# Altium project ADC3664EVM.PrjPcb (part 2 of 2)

## Sheet ADC Inputs.SchDoc: ADC Inputs
size 431 x 279 mm; Date: Not shown in title block; ApprovedBy: Not shown in title block; CheckedBy: Not shown in title block; Author: Not shown in title block; CompanyName: Not shown in title block; Engineer: Not shown in title block; Organization: Not shown in title block; Address1: Not shown in title block; Address2: Not shown in title block; Address3: Not shown in title block; Address4: Not shown in title block; DocumentNumber: 1; Revision: Use project parameter SCH_Rev; SheetNumber: 9; SheetTotal: 14; PageSetup: Record=PageOptions¦CenterHorizontal=True¦CenterVertical=True¦PrintScale=1.00¦XCorrection=1.00¦YCorrection=1.00¦PrintKind=0¦BorderSize=5000000¦LeftOffset=0¦BottomOffset=0¦Orientation=2¦PaperLength=1000¦PaperWidth=1000¦Scale=100¦PaperSource=15¦PrintQuality=600¦MediaType=1¦DitherType=10¦PaperKind=Letter¦PrintScaleMode=1
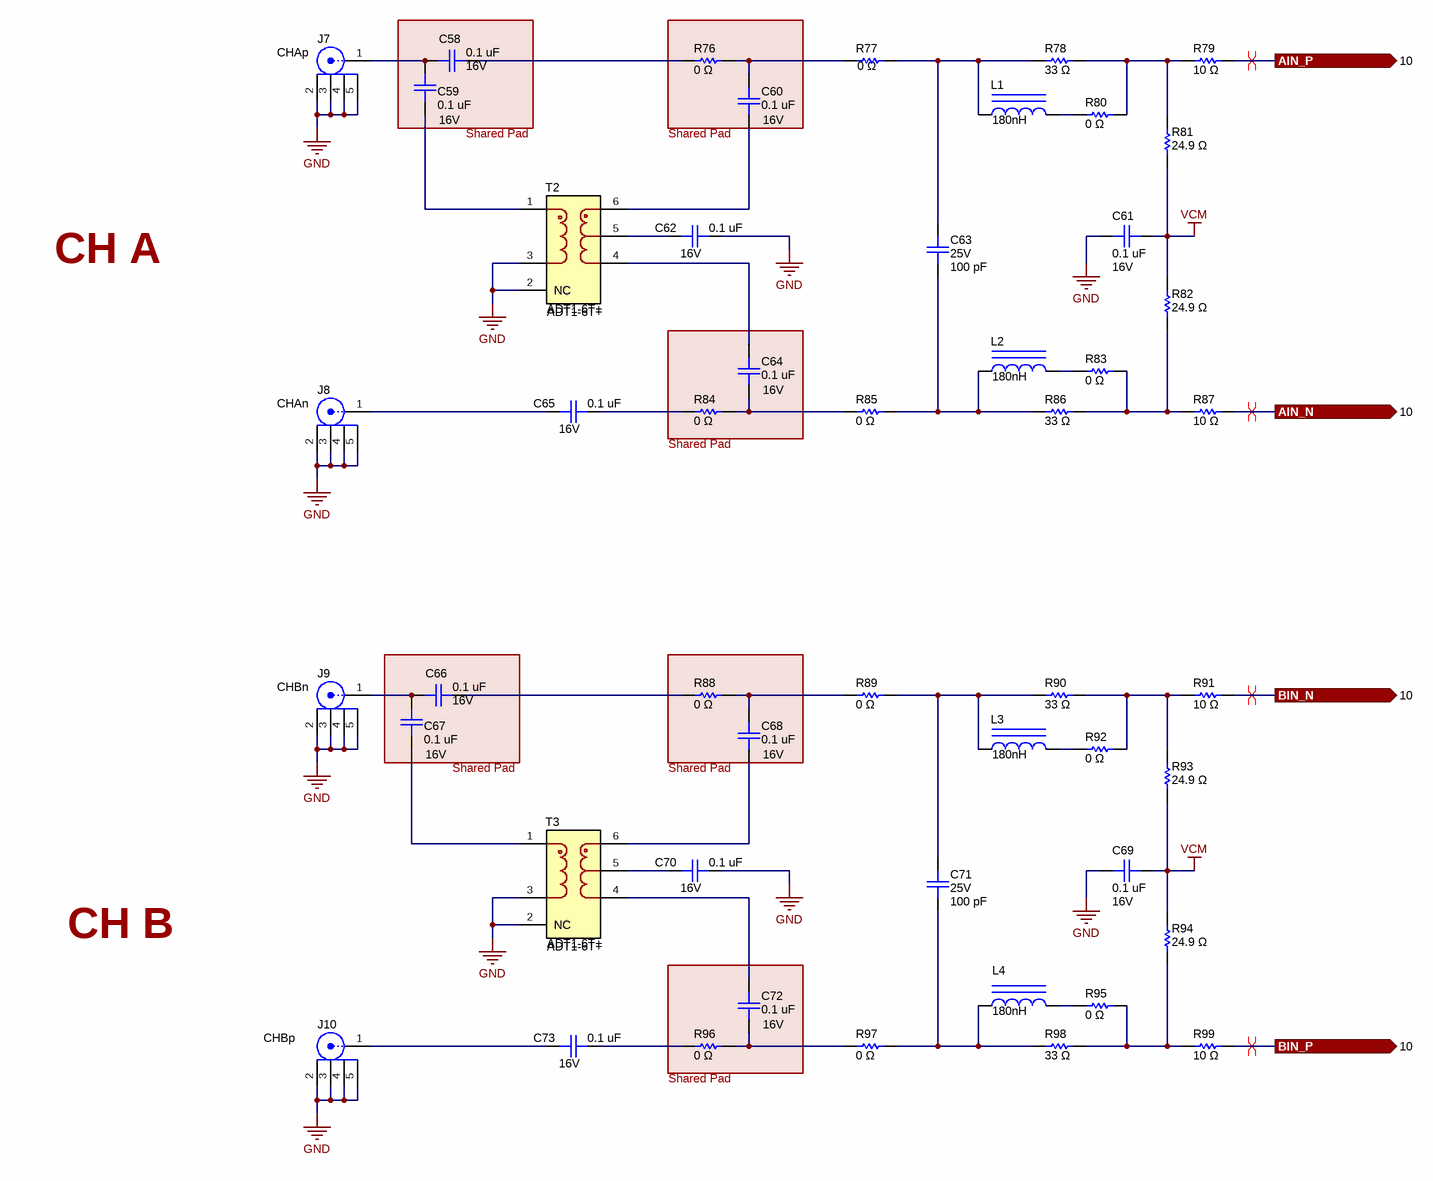
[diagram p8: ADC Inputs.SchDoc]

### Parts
(Parts that share a designator on the sheet are numbered #1, #2 ... from top to bottom, then left to right.)
?#4  Shared Pad  (graphical)
?#5  Shared Pad  (graphical)
?#6  Shared Pad  (graphical)
?#7  Shared Pad  (graphical)
?#8  Shared Pad  (graphical)
?#9  Shared Pad  (graphical)
C58  value 0.1 uF  Voltage - Rated: 16V  [0201_cap]  (hidden comment: GRM033Z71C104ME14D)
C59  value 0.1 uF  Voltage - Rated: 16V  [0201_cap]  (hidden comment: GRM033Z71C104ME14D)
C60  value 0.1 uF  Voltage - Rated: 16V  [0201_cap]  (hidden comment: GRM033Z71C104ME14D)
C61  value 0.1 uF  Voltage - Rated: 16V  [0201_cap]  (hidden comment: GRM033Z71C104ME14D)
C62  value 0.1 uF  Voltage - Rated: 16V  [0201_cap]  (hidden comment: GRM033Z71C104ME14D)
C63  value 100 pF  Voltage - Rated: 25V  [0201_cap]  (hidden comment: CGA1A2X7R1E101M030BA)
C64  value 0.1 uF  Voltage - Rated: 16V  [0201_cap]  (hidden comment: GRM033Z71C104ME14D)
C65  value 0.1 uF  Voltage - Rated: 16V  [0201_cap]  (hidden comment: GRM033Z71C104ME14D)
C66  value 0.1 uF  Voltage - Rated: 16V  [0201_cap]  (hidden comment: GRM033Z71C104ME14D)
C67  value 0.1 uF  Voltage - Rated: 16V  [0201_cap]  (hidden comment: GRM033Z71C104ME14D)
C68  value 0.1 uF  Voltage - Rated: 16V  [0201_cap]  (hidden comment: GRM033Z71C104ME14D)
C69  value 0.1 uF  Voltage - Rated: 16V  [0201_cap]  (hidden comment: GRM033Z71C104ME14D)
C70  value 0.1 uF  Voltage - Rated: 16V  [0201_cap]  (hidden comment: GRM033Z71C104ME14D)
C71  value 100 pF  Voltage - Rated: 25V  [0201_cap]  (hidden comment: CGA1A2X7R1E101M030BA)
C72  value 0.1 uF  Voltage - Rated: 16V  [0201_cap]  (hidden comment: GRM033Z71C104ME14D)
C73  value 0.1 uF  Voltage - Rated: 16V  [0201_cap]  (hidden comment: GRM033Z71C104ME14D)
J7  Text1: CHAp  [FP-132134-15_CONN_SMA_JACK-MFG]  (hidden comment: 132134-15)
J8  Text1: CHAn  [FP-132134-15_CONN_SMA_JACK-MFG]  (hidden comment: 132134-15)
J9  Text1: CHBn  [FP-132134-15_CONN_SMA_JACK-MFG]  (hidden comment: 132134-15)
J10  Text1: CHBp  [FP-132134-15_CONN_SMA_JACK-MFG]  (hidden comment: 132134-15)
L1  value 180nH  [IND_LQG15H]  (hidden comment: LQG15HSR18J02D)
L2  value 180nH  [IND_LQG15H]  (hidden comment: LQG15HSR18J02D)
L3  value 180nH  [IND_LQG15H]  (hidden comment: LQG15HSR18J02D)
L4  value 180nH  [IND_LQG15H]  (hidden comment: LQG15HSR18J02D)
R76  value 0 Ω  [0201]  (hidden comment: ERJ-1GN0R00C)
R77  value 0 Ω  [0201]  (hidden comment: ERJ-1GN0R00C)
R78  value 33 Ω  [0201]  (hidden comment: ERJ-1GNF33R0C)
R79  value 10 Ω  [0201]  (hidden comment: ERJ-1GNF10R0C)
R80  value 0 Ω  [0201]  (hidden comment: ERJ-1GN0R00C)
R81  value 24.9 Ω  [0201]  (hidden comment: ERJ-1GNF24R9C)
R82  value 24.9 Ω  [0201]  (hidden comment: ERJ-1GNF24R9C)
R83  value 0 Ω  [0201]  (hidden comment: ERJ-1GN0R00C)
R84  value 0 Ω  [0201]  (hidden comment: ERJ-1GN0R00C)
R85  value 0 Ω  [0201]  (hidden comment: ERJ-1GN0R00C)
R86  value 33 Ω  [0201]  (hidden comment: ERJ-1GNF33R0C)
R87  value 10 Ω  [0201]  (hidden comment: ERJ-1GNF10R0C)
R88  value 0 Ω  [0201]  (hidden comment: ERJ-1GN0R00C)
R89  value 0 Ω  [0201]  (hidden comment: ERJ-1GN0R00C)
R90  value 33 Ω  [0201]  (hidden comment: ERJ-1GNF33R0C)
R91  value 10 Ω  [0201]  (hidden comment: ERJ-1GNF10R0C)
R92  value 0 Ω  [0201]  (hidden comment: ERJ-1GN0R00C)
R93  value 24.9 Ω  [0201]  (hidden comment: ERJ-1GNF24R9C)
R94  value 24.9 Ω  [0201]  (hidden comment: ERJ-1GNF24R9C)
R95  value 0 Ω  [0201]  (hidden comment: ERJ-1GN0R00C)
R96  value 0 Ω  [0201]  (hidden comment: ERJ-1GN0R00C)
R97  value 0 Ω  [0201]  (hidden comment: ERJ-1GN0R00C)
R98  value 33 Ω  [0201]  (hidden comment: ERJ-1GNF33R0C)
R99  value 10 Ω  [0201]  (hidden comment: ERJ-1GNF10R0C)
T2  ADT1-6T+  [CD637]
T3  ADT1-6T+  [CD637]

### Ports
AIN_N (out, see 10), AIN_P (out, see 10), BIN_N (out, see 10), BIN_P (out, see 10)

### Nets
GND: C61.1 C62.2 C69.1 C70.2 J7.2 J7.3 J7.4 J7.5 J8.2 J8.3 J8.4 J8.5 J9.2 J9.3 J9.4 J9.5 J10.2 J10.3 J10.4 J10.5 T2.2(NC) T2.3 T3.2(NC) T3.3
VCM: C61.2 C69.2 R81.1 R82.2 R93.1 R94.2
AIN_N: R87.2 ; port AIN_N
AIN_P: R79.2 ; port AIN_P
BIN_N: R91.2 ; port BIN_N
BIN_P: R99.2 ; port BIN_P
NetC58_1: C58.1 C59.1 J7.1
NetC58_2: C58.2 R76.1
NetC59_2: C59.2 T2.1
NetC60_1: C60.1 T2.6
NetC60_2: C60.2 R76.2 R77.1
NetC62_1: C62.1 T2.5
NetC63_1: C63.1 L2.1 R85.2 R86.1
NetC63_2: C63.2 L1.1 R77.2 R78.1
NetC64_1: C64.1 R84.2 R85.1
NetC64_2: C64.2 T2.4
NetC65_1: C65.1 J8.1
NetC65_2: C65.2 R84.1
NetC66_1: C66.1 C67.1 J9.1
NetC66_2: C66.2 R88.1
NetC67_2: C67.2 T3.1
NetC68_1: C68.1 T3.6
NetC68_2: C68.2 R88.2 R89.1
NetC70_1: C70.1 T3.5
NetC71_1: C71.1 L4.1 R97.2 R98.1
NetC71_2: C71.2 L3.1 R89.2 R90.1
NetC72_1: C72.1 R96.2 R97.1
NetC72_2: C72.2 T3.4
NetC73_1: C73.1 J10.1
NetC73_2: C73.2 R96.1
NetL1_2: L1.2 R80.1
NetL2_2: L2.2 R83.1
NetL3_2: L3.2 R92.1
NetL4_2: L4.2 R95.1
NetR78_2: R78.2 R79.1 R80.2 R81.2
NetR82_1: R82.1 R83.2 R86.2 R87.1
NetR90_2: R90.2 R91.1 R92.2 R93.2
NetR94_1: R94.1 R95.2 R98.2 R99.1

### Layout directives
differential pair: AIN_N, AIN_P, BIN_N, BIN_P

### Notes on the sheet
- CH A
- CH B

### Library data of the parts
?#4-?#9 = Swizzle: Schematic notation to show that the pads of two components should be overlapped
C58-C62 C64-C70 C72 C73 = capcc09270: CAP CER 0.1UF 16V X7R 0201; Manufacturer: Murata Electronics; CompType: Capacitor Ceramic; Tolerance: ±20%; SizeX_mm: 0.6; SizeY_mm: 0.3; SizeZ_mm: 0.33
C63 C71 = capcc06388: CAP CER 100PF 25V X7R 0201; Manufacturer: TDK Corporation; CompType: Capacitor Ceramic; Tolerance: ±20%; SizeX_mm: 0.6; SizeY_mm: 0.3; SizeZ_mm: 0.33
J7-J10 = 132134-15: SMA Connector Jack, Female Socket 50Ohm Surface Mount, Through Hole Solder; Manufacturer: Amphenol RF; UniqueID: cmp00028; CompType: RF Connector
L1-L4 = LQG15HSR18J02D: Inductor, Multilayer, Air Core, 180 nH, 0.14 A, 3.38 ohm, SMD; Manufacturer: MuRata; Isat: 0.14A @ % inductance drop; Irms: 0.14A @ C rise; Green_Lifecycle: Active; SizeAreaWB_mm2: 3; DCR_ohm: 3.38; Green_REACh: Passed; Imax_A: 140mA; SizeZ_mm: 0.55; SizeX_mm: 1; SizeY_mm: 0.5; Value2: 0.14A; AEC Category: Q200
R76 R77 R80 R83-R85 R88 R89 R92 R95-R97 = RSMD020101699: RES SMD 0 OHM JUMPER 1/20W 0201; Manufacturer: Panasonic Electronic Components; CompType: Resistor SMD; Power (Watts): 0.05W, 1/20W
R78 R86 R90 R98 = RSMD020100013: RES SMD 33 OHM 1% 1/20W 0201; Manufacturer: Panasonic Electronic Components; CompType: Resistor SMD; Power (Watts): 0.05W, 1/20W; Temperature Coefficient: ±200ppm/°C
R79 R87 R91 R99 = RSMD020100179: RES SMD 10 OHM 1% 1/20W 0201; Manufacturer: Panasonic Electronic Components; CompType: Resistor SMD; Power (Watts): 0.05W, 1/20W; Temperature Coefficient: ±200ppm/°C
R81 R82 R93 R94 = RSMD020100010: RES SMD 24.9 OHM 1% 1/20W 0201; Manufacturer: Panasonic Electronic Components; CompType: Resistor SMD; Power (Watts): 0.05W, 1/20W; Temperature Coefficient: ±200ppm/°C
T2 T3 = ADT1-6T+: Transformer 50Ω/0.03 to 125 MHz; Manufacturer: Mini-Circuits; Rsec1_ohm: 50; Symbol Name: SYM-ADT1-6T+; Ns1toNp: 1:1; SizeZ_mm: .206inch; AEC Qualified: No

## Sheet DUT IO.SchDoc: ADC IO
size 431 x 279 mm; Date: Not shown in title block; ApprovedBy: Not shown in title block; CheckedBy: Not shown in title block; Author: Not shown in title block; CompanyName: Not shown in title block; Engineer: Not shown in title block; Organization: Not shown in title block; Address1: Not shown in title block; Address2: Not shown in title block; Address3: Not shown in title block; Address4: Not shown in title block; DocumentNumber: 1; Revision: Use project parameter SCH_Rev; SheetNumber: 10; SheetTotal: 14; PageSetup: Record=PageOptions¦CenterHorizontal=True¦CenterVertical=True¦PrintScale=1.00¦XCorrection=1.00¦YCorrection=1.00¦PrintKind=0¦BorderSize=5000000¦LeftOffset=0¦BottomOffset=0¦Orientation=2¦PaperLength=1000¦PaperWidth=1000¦Scale=100¦PaperSource=15¦PrintQuality=600¦MediaType=1¦DitherType=10¦PaperKind=Letter¦PrintScaleMode=1
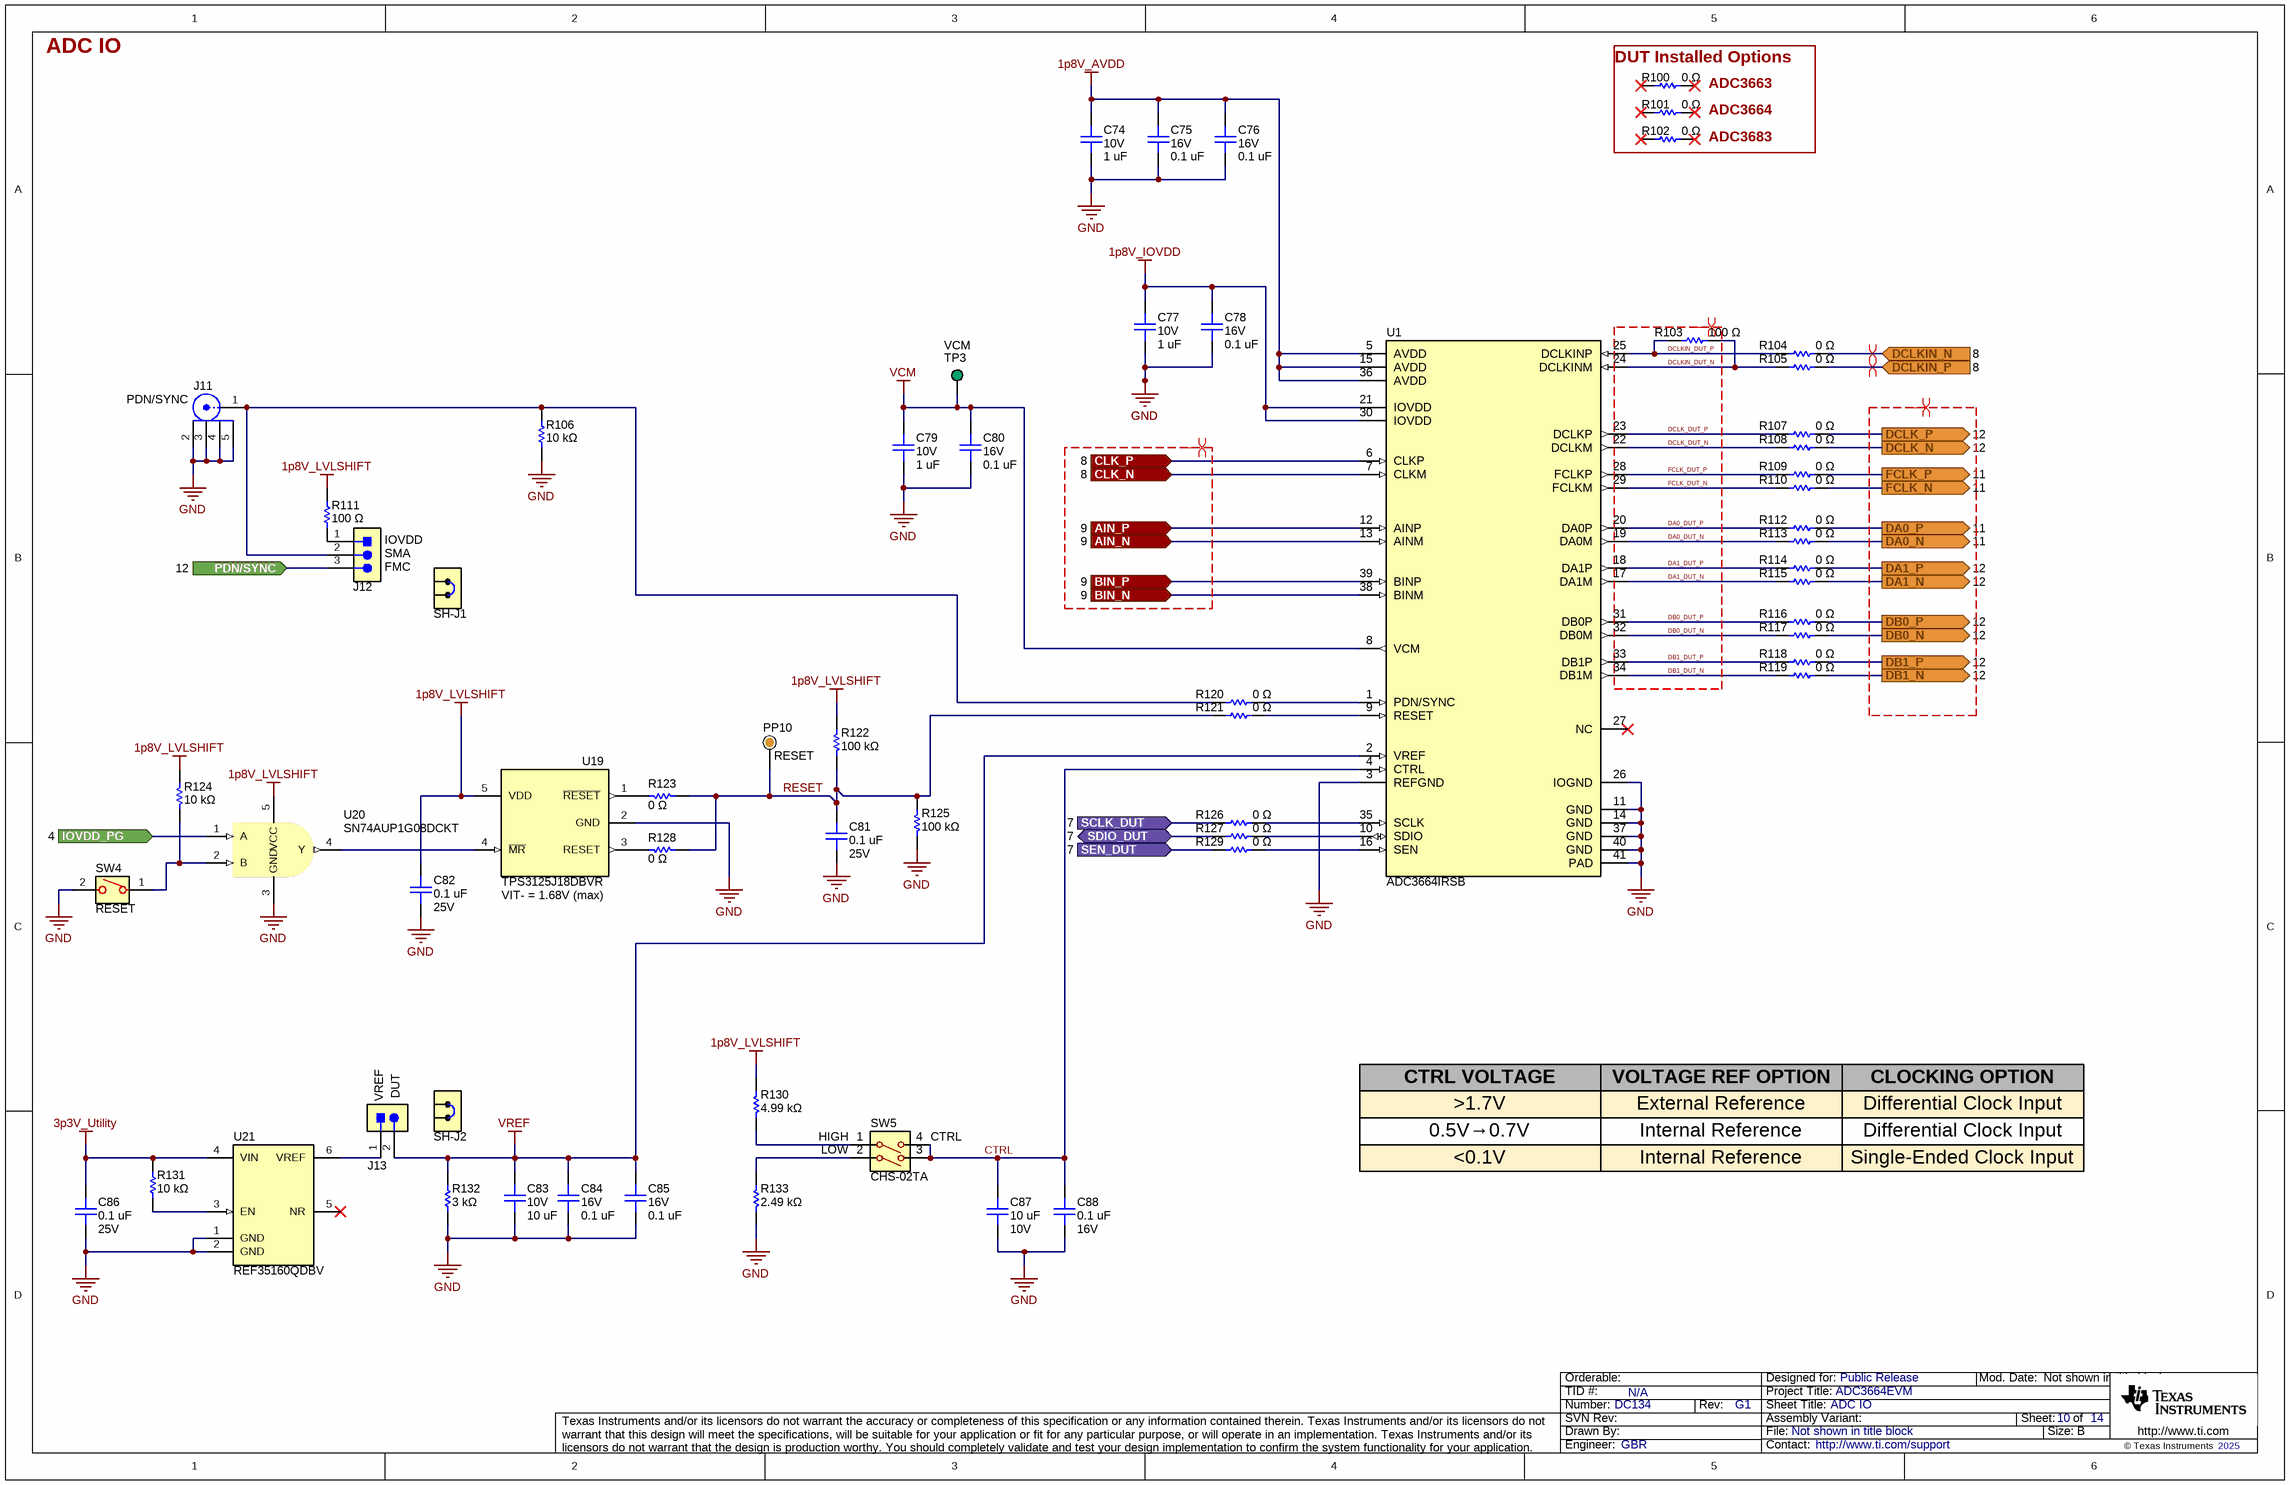
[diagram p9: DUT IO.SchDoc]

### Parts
C74  value 1 uF  Voltage - Rated: 10V  [0201_cap]  (hidden comment: GRM033R61A105ME44D)
C75  value 0.1 uF  Voltage - Rated: 16V  [0201_cap]  (hidden comment: GRM033Z71C104ME14D)
C76  value 0.1 uF  Voltage - Rated: 16V  [0201_cap]  (hidden comment: GRM033Z71C104ME14D)
C77  value 1 uF  Voltage - Rated: 10V  [0201_cap]  (hidden comment: GRM033R61A105ME44D)
C78  value 0.1 uF  Voltage - Rated: 16V  [0201_cap]  (hidden comment: GRM033Z71C104ME14D)
C79  value 1 uF  Voltage - Rated: 10V  [0201_cap]  (hidden comment: GRM033R61A105ME44D)
C80  value 0.1 uF  Voltage - Rated: 16V  [0201_cap]  (hidden comment: GRM033Z71C104ME14D)
C81  value 0.1 uF  Voltage - Rated: 25V  [0402L_cap]  (hidden comment: GRT155R71E104KE01J)
C82  value 0.1 uF  Voltage - Rated: 25V  [0402L_cap]  (hidden comment: GRT155R71E104KE01J)
C83  value 10 uF  Voltage - Rated: 10V  [0402L_cap]  (hidden comment: 0402ZD106MAT2A)
C84  value 0.1 uF  Voltage - Rated: 16V  [0201_cap]  (hidden comment: GRM033Z71C104ME14D)
C85  value 0.1 uF  Voltage - Rated: 16V  [0201_cap]  (hidden comment: GRM033Z71C104ME14D)
C86  value 0.1 uF  Voltage - Rated: 25V  [0402L_cap]  (hidden comment: GRT155R71E104KE01J)
C87  value 10 uF  Voltage - Rated: 10V  [0402L_cap]  (hidden comment: 0402ZD106MAT2A)
C88  value 0.1 uF  Voltage - Rated: 16V  [0201_cap]  (hidden comment: GRM033Z71C104ME14D)
J11  Text1: PDN/SYNC  [FP-132134-15_CONN_SMA_JACK-MFG]  (hidden comment: 132134-15)
J12  Text3: FMC  Text2: SMA  Text1: IOVDD  [PBC03SAAN]  (hidden comment: TSW-103-14-L-S)
J13  Text2: DUT  Text1: VREF  [HDR_2x1_TH_VT_50mil]  (hidden comment: GRPB021VWVN-RC)
PP10  Text1: RESET  [ProbePoint_TH_40mil]  (hidden comment: Probe Point)  (no BOM)
R100  value 0 Ω  [0805L]  (hidden comment: ERJ-6GEY0R00V)
R101  value 0 Ω  [0805L]  (hidden comment: ERJ-6GEY0R00V)
R102  value 0 Ω  [0805L]  (hidden comment: ERJ-6GEY0R00V)
R103  value 100 Ω  [0201]  (hidden comment: ERJ-1GNF1000C)
R104  value 0 Ω  [0201]  (hidden comment: ERJ-1GN0R00C)
R105  value 0 Ω  [0201]  (hidden comment: ERJ-1GN0R00C)
R106  value 10 kΩ  [0402L]  (hidden comment: ERA-2AEB103X)
R107  value 0 Ω  [0201]  (hidden comment: ERJ-1GN0R00C)
R108  value 0 Ω  [0201]  (hidden comment: ERJ-1GN0R00C)
R109  value 0 Ω  [0201]  (hidden comment: ERJ-1GN0R00C)
R110  value 0 Ω  [0201]  (hidden comment: ERJ-1GN0R00C)
R111  value 100 Ω  [0402L]  (hidden comment: ERJ-2GEJ101X)
R112  value 0 Ω  [0201]  (hidden comment: ERJ-1GN0R00C)
R113  value 0 Ω  [0201]  (hidden comment: ERJ-1GN0R00C)
R114  value 0 Ω  [0201]  (hidden comment: ERJ-1GN0R00C)
R115  value 0 Ω  [0201]  (hidden comment: ERJ-1GN0R00C)
R116  value 0 Ω  [0201]  (hidden comment: ERJ-1GN0R00C)
R117  value 0 Ω  [0201]  (hidden comment: ERJ-1GN0R00C)
R118  value 0 Ω  [0201]  (hidden comment: ERJ-1GN0R00C)
R119  value 0 Ω  [0201]  (hidden comment: ERJ-1GN0R00C)
R120  value 0 Ω  [0201]  (hidden comment: ERJ-1GN0R00C)
R121  value 0 Ω  [0201]  (hidden comment: ERJ-1GN0R00C)
R122  value 100 kΩ  [0402L]  (hidden comment: ERJ-2GEJ104X)
R123  value 0 Ω  [0402L]  (hidden comment: ERJ-U020R00X)
R124  value 10 kΩ  [0402L]  (hidden comment: ERA-2AEB103X)
R125  value 100 kΩ  [0402L]  (hidden comment: ERJ-2GEJ104X)
R126  value 0 Ω  [0201]  (hidden comment: ERJ-1GN0R00C)
R127  value 0 Ω  [0201]  (hidden comment: ERJ-1GN0R00C)
R128  value 0 Ω  [0402L]  (hidden comment: ERJ-U020R00X)
R129  value 0 Ω  [0201]  (hidden comment: ERJ-1GN0R00C)
R130  value 4.99 kΩ  [0201]  (hidden comment: ERJ-1GNF4991C)
R131  value 10 kΩ  [0402L]  (hidden comment: ERA-2AEB103X)
R132  value 3 kΩ  [0201]  (hidden comment: ERJ-1GNF3001C)
R133  value 2.49 kΩ  [0201]  (hidden comment: ERJ-1GNF2491C)
SH-J1  SPC02SYAN  [SPC02SYAN]  (value not drawn)
SH-J2  HMSC-G  [HMSC-G]  (value not drawn)
SW4  Text1: RESET  [FSMSM]  (hidden comment: FSMSM)
SW5  CHS-02TA  Text4: CTRL  Text2: LOW  Text1: HIGH  [CHS-02TA]
TP3  Text1: VCM  [KEYSTONE5116]  (hidden comment: 5116)
U1  ADC3664IRSB  [RSB0040E]
U19  TPS3125J18DBVR  Text1: VIT- = 1.68V (max)  [DBV0005A]
U20  SN74AUP1G08DCKT  [DCK0005A]
U21  REF35160QDBV  [DBV0006A]

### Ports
AIN_N (in, see 9), AIN_P (in, see 9), BIN_N (in, see 9), BIN_P (in, see 9), CLK_N (in, see 8), CLK_P (in, see 8), DA0_N (out, see 11), DA0_P (out, see 11), DA1_N (out, see 12), DA1_P (out, see 12), DB0_N (out, see 12), DB0_P (out, see 12), DB1_N (out, see 12), DB1_P (out, see 12), DCLK_N (out, see 12), DCLK_P (out, see 12), DCLKIN_N (in, see 8), DCLKIN_P (in, see 8), FCLK_N (out, see 11), FCLK_P (out, see 11), IOVDD_PG (in, see 4), PDN/SYNC (in, see 12), SCLK_DUT (in, see 7), SDIO_DUT (bidir, see 7), SEN_DUT (in, see 7)

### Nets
1p8V_AVDD: C74.2 C75.2 C76.2 U1.5(AVDD) U1.15(AVDD) U1.36(AVDD)
1p8V_IOVDD: C77.2 C78.2 U1.21(IOVDD) U1.30(IOVDD)
1p8V_LVLSHIFT: C82.2 R111.2 R122.2 R124.1 R130.2 U19.5(VDD) U20.5(VCC)
3p3V_Utility: C86.2 R131.2 U21.4(VIN)
GND: C74.1 C75.1 C76.1 C77.1 C78.1 C79.1 C80.1 C81.1 C82.1 C83.1 C84.1 C85.1 C86.1 C87.1 C88.1 J11.2 J11.3 J11.4 J11.5 R106.1 R125.1 R132.1 R133.1 SW4.2 U1.3(REFGND) U1.11(GND) U1.14(GND) U1.26(IOGND) U1.37(GND) U1.40(GND) U1.41(PAD) U19.2(GND) U20.3(GND) U21.1(GND) U21.2(GND)
VCM: C79.2 C80.2 TP3.1 U1.8(VCM)
VREF: C83.2 C84.2 C85.2 J13.2 R132.2 U1.2(VREF)
AIN_N: U1.13(AINM) ; port AIN_N
AIN_P: U1.12(AINP) ; port AIN_P
BIN_N: U1.38(BINM) ; port BIN_N
BIN_P: U1.39(BINP) ; port BIN_P
CLK_N: U1.7(CLKM) ; port CLK_N
CLK_P: U1.6(CLKP) ; port CLK_P
CTRL: C87.2 C88.2 SW5.3(OFF) SW5.4(OFF) U1.4(CTRL)
DA0_DUT_N: R113.1 U1.19(DA0M)
DA0_DUT_P: R112.1 U1.20(DA0P)
DA0_N: R113.2 ; port DA0_N
DA0_P: R112.2 ; port DA0_P
DA1_DUT_N: R115.1 U1.17(DA1M)
DA1_DUT_P: R114.1 U1.18(DA1P)
DA1_N: R115.2 ; port DA1_N
DA1_P: R114.2 ; port DA1_P
DB0_DUT_N: R117.1 U1.32(DB0M)
DB0_DUT_P: R116.1 U1.31(DB0P)
DB0_N: R117.2 ; port DB0_N
DB0_P: R116.2 ; port DB0_P
DB1_DUT_N: R119.1 U1.34(DB1M)
DB1_DUT_P: R118.1 U1.33(DB1P)
DB1_N: R119.2 ; port DB1_N
DB1_P: R118.2 ; port DB1_P
DCLK_DUT_N: R108.1 U1.22(DCLKM)
DCLK_DUT_P: R107.1 U1.23(DCLKP)
DCLK_N: R108.2 ; port DCLK_N
DCLK_P: R107.2 ; port DCLK_P
DCLKIN_DUT_N: R103.2 R105.1 U1.24(DCLKINM)
DCLKIN_DUT_P: R103.1 R104.1 U1.25(DCLKINP)
DCLKIN_N: R104.2 ; port DCLKIN_N
DCLKIN_P: R105.2 ; port DCLKIN_P
FCLK_DUT_N: R110.1 U1.29(FCLKM)
FCLK_DUT_P: R109.1 U1.28(FCLKP)
FCLK_N: R110.2 ; port FCLK_N
FCLK_P: R109.2 ; port FCLK_P
IOVDD_PG: U20.1(A) ; port IOVDD_PG
PDN/SYNC: J12.3 ; port PDN/SYNC
RESET: C81.2 PP10.1 R121.1 R122.1 R123.1 R125.2 R128.1
SCLK_DUT: R126.1 ; port SCLK_DUT
SDIO_DUT: R127.1 ; port SDIO_DUT
SEN_DUT: R129.1 ; port SEN_DUT
NetJ11_1: J11.1 J12.2 R106.2 R120.1
NetJ12_1: J12.1 R111.1
NetJ13_1: J13.1 U21.6(VREF)
NetR120_2: R120.2 U1.1(PDN/SYNC)
NetR121_2: R121.2 U1.9(RESET)
NetR123_2: R123.2 U19.1(~{RESET})
NetR124_2: R124.2 SW4.1 U20.2(B)
NetR126_2: R126.2 U1.35(SCLK)
NetR127_2: R127.2 U1.10(SDIO)
NetR128_2: R128.2 U19.3(RESET)
NetR129_2: R129.2 U1.16(SEN)
NetR130_1: R130.1 SW5.1(ON)
NetR131_1: R131.1 U21.3(EN)
NetR133_2: R133.2 SW5.2(ON)
NetU19_4: U19.4(~{MR}) U20.4(Y)

Not connected (* = marked no-connect by the designer): R100 1* 2*; R101 1* 2*; R102 1* 2*; U1 27(NC)*; U21 5(NR)*

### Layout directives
differential pair; net class DiffPair: DA0_DUT_N, DA0_DUT_P, DA1_DUT_N, DA1_DUT_P, DB0_DUT_N, DB0_DUT_P, DB1_DUT_N, DB1_DUT_P, DCLK_DUT_N, DCLK_DUT_P, DCLKIN_DUT_N, DCLKIN_DUT_P, FCLK_DUT_N, FCLK_DUT_P
differential pair; net class DiffPairIN: (no net found under the mark)
differential pair: (no net found under the mark), DCLKIN_N, DCLKIN_P

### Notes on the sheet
- ADC3663
- DUT Installed Options
- ADC3664
- ADC3683
- CTRL VOLTAGE
- VOLTAGE REF OPTION
- CLOCKING OPTION
- >1.7V
- 0.5V→0.7V
- <0.1V
- External Reference
- Internal Reference
- Differential Clock Input
- Single-Ended Clock Input

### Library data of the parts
C74 C77 C79 = capcc09264: CAP CER 1UF 10V X5R 0201; Manufacturer: Murata Electronics; CompType: Capacitor Ceramic; Tolerance: ±20%; SizeX_mm: 0.6; SizeY_mm: 0.3; SizeZ_mm: 0.33
C75 C76 C78 C80 C84 C85 C88 = capcc09270: as C58-C62 on sheet ADC Inputs
C81 C82 C86 = capcc09401: CAP CER 0.1UF 25V X7R 0402; Manufacturer: Murata; CompType: Capacitor Ceramic; Tolerance: ±10%; SizeX_mm: 1; SizeY_mm: 0.5; SizeZ_mm: 0.7
C83 C87 = capcc09406: CAP CER 10UF 10V X5R 0402; Manufacturer: KYOCERA AVX; CompType: Capacitor Ceramic; Tolerance: ±20%; SizeX_mm: 1; SizeY_mm: 0.5; SizeZ_mm: 0.7
J11 = 132134-15: as J7-J10 on sheet ADC Inputs
J12 = TSW-103-14-L-S: Header, 100mil, 3x1, Gold, TH; Manufacturer: Samtec; Alt Manufacturer: Sullins Connector Solutions; UniqueID: cmp00015; Pitch (mm): 2.54
J13 = cmp00298: Header, 50mil, 2x1, Gold, TH; Manufacturer: Sullins Connector Solutions; Pitch (mm): 1.27
PP10 = Probe Point: Probe Point that can be used in lue of a test point; UniqueID: cmp00025
R100-R102 = RSMD080510615: RES SMD 0 OHM JUMPER 1/8W 0805; Manufacturer: Panasonic Electronic Components; CompType: Resistor SMD; Power (Watts): 0.125W, 1/8W; SizeX_mm: 2; SizeY_mm: 1.25; SizeZ_mm: 0.7
R103 = RSMD020100289: RES SMD 100 OHM 1% 1/20W 0201; Manufacturer: Panasonic Electronic Components; CompType: Resistor SMD; Power (Watts): 0.05W, 1/20W; Temperature Coefficient: ±200ppm/°C
R104 R105 R107-R110 R112-R121 R126 R127 R129 = RSMD020101699: as R76 on sheet ADC Inputs
R106 R124 R131 = RSMD040200315: RES SMD 10K OHM 0.1% 1/16W 0402; Manufacturer: Panasonic Electronic Components; CompType: Resistor SMD; Power (Watts): 0.063W, 1/16W; Temperature Coefficient: ±25ppm/°C; SizeX_mm: 1; SizeY_mm: 0.5; SizeZ_mm: 0.4
R111 = RSMD040200370: RES SMD 100 OHM 5% 1/10W 0402; Manufacturer: Panasonic Electronic Components; CompType: Resistor SMD; Power (Watts): 0.1W, 1/10W; Temperature Coefficient: ±200ppm/°C; SizeX_mm: 1; SizeY_mm: 0.5; SizeZ_mm: 0.4
R122 R125 = RSMD040200354: RES SMD 100K OHM 5% 1/10W 0402; Manufacturer: Panasonic Electronic Components; CompType: Resistor SMD; Power (Watts): 0.1W, 1/10W; Temperature Coefficient: ±200ppm/°C; SizeX_mm: 1; SizeY_mm: 0.5; SizeZ_mm: 0.4
R123 R128 = RSMD040200004: RES 0 OHM JUMPER 0402 SMD; Manufacturer: Panasonic Electronic Components; CompType: Resistor SMD; Power (Watts): 0.1W, 1/10W; Temperature Coefficient: -100/ +600ppm/°C; SizeX_mm: 1; SizeY_mm: 0.5; SizeZ_mm: 0.4
R130 = RSMD020100641: RES SMD 4.99K OHM 1% 1/20W 0201; Manufacturer: Panasonic Electronic Components; CompType: Resistor SMD; Power (Watts): 0.05W, 1/20W; Temperature Coefficient: ±200ppm/°C
R132 = RSMD020100769: RES SMD 3K OHM 1% 1/20W 0201; Manufacturer: Panasonic Electronic Components; CompType: Resistor SMD; Power (Watts): 0.05W, 1/20W; Temperature Coefficient: ±200ppm/°C
R133 = RSMD020100692: RES SMD 2.49K OHM 1% 1/20W 0201; Manufacturer: Panasonic Electronic Components; CompType: Resistor SMD; Power (Watts): 0.05W, 1/20W; Temperature Coefficient: ±200ppm/°C
SH-J1 = cmp00094: 2 (1 x 2) Position Shunt Connector Black Open Top 0.100" (2.54mm) Gold; Manufacturer: Sullins; PartNumber: QPC02SXGN-RC; Value: 1x2; Note: You can "mate" this to a header by matching the designator.  i.e. use SH-J3 for header J3; Pitch (mm): 2.54
SH-J2 = HMSC-G: 2 (1 x 2) Position Shunt Connector Black Closed Top 0.050" (1.27mm) Gold; Manufacturer: Adam Tech; Value: 1x2; Key: SPC02SYAN; Note: You can "mate" this to a header by matching the designator.  i.e. use SH-J3 for header J3; Pitch (mm): 1.27
SW4 = cmp00234: SWITCH TACTILE SPST-NO 0.05A 24V; Manufacturer: TE Connectivity; CompType: Push Button
SW5 = CHS-02TA: SWITCH SLIDE DIP SPST 0.1A 6V; Manufacturer: Nidec Components Corporation; CompType: Swtich
TP3 = cmp00057: Test Point, Miniature, Green, TH; Manufacturer: Keystone
U1 = ADC3664IRSB: Dual-channel, 14-bit, 125-MSPS, high-SNR, low-power ADC with SLVDS interface; PartNumber: ADC3664IRSBR; Manufacturer: Texas Instruments; Alt PartNumber: ADC3664IRSBT
U19 = cmp00229: Push-pull, supply voltage supervisor with manual reset; Manufacturer: Texas Instruments; Alt PartNumber: TPS3125J18DBVT; CompType: Voltage Detector
U20 = cmp00268: SN74AUP1G08 Low-Power Single 2-Input Positive-AND Gate; Manufacturer: Texas Instruments
U21 = cmp00301: Ultra Low-Power, High-Precision Voltage Reference; Manufacturer: Texas Instruments; Pitch (mm): 1.27

## Sheet FMC+ Sections A-E.SchDoc: FMC+ Section Rows A - E
size 431 x 279 mm; Date: Not shown in title block; ApprovedBy: Not shown in title block; CheckedBy: Not shown in title block; Author: Not shown in title block; CompanyName: Not shown in title block; Engineer: Not shown in title block; Organization: Not shown in title block; Address1: Not shown in title block; Address2: Not shown in title block; Address3: Not shown in title block; Address4: Not shown in title block; DocumentNumber: 2; Revision: Use project parameter SCH_Rev; SheetNumber: 11; SheetTotal: 14; PageSetup: Record=PageOptions¦CenterHorizontal=True¦CenterVertical=True¦PrintScale=1.00¦XCorrection=1.00¦YCorrection=1.00¦PrintKind=0¦BorderSize=5000000¦LeftOffset=0¦BottomOffset=0¦Orientation=2¦PaperLength=1000¦PaperWidth=1000¦Scale=100¦PaperSource=15¦PrintQuality=600¦MediaType=1¦DitherType=10¦PaperKind=Letter¦PrintScaleMode=1
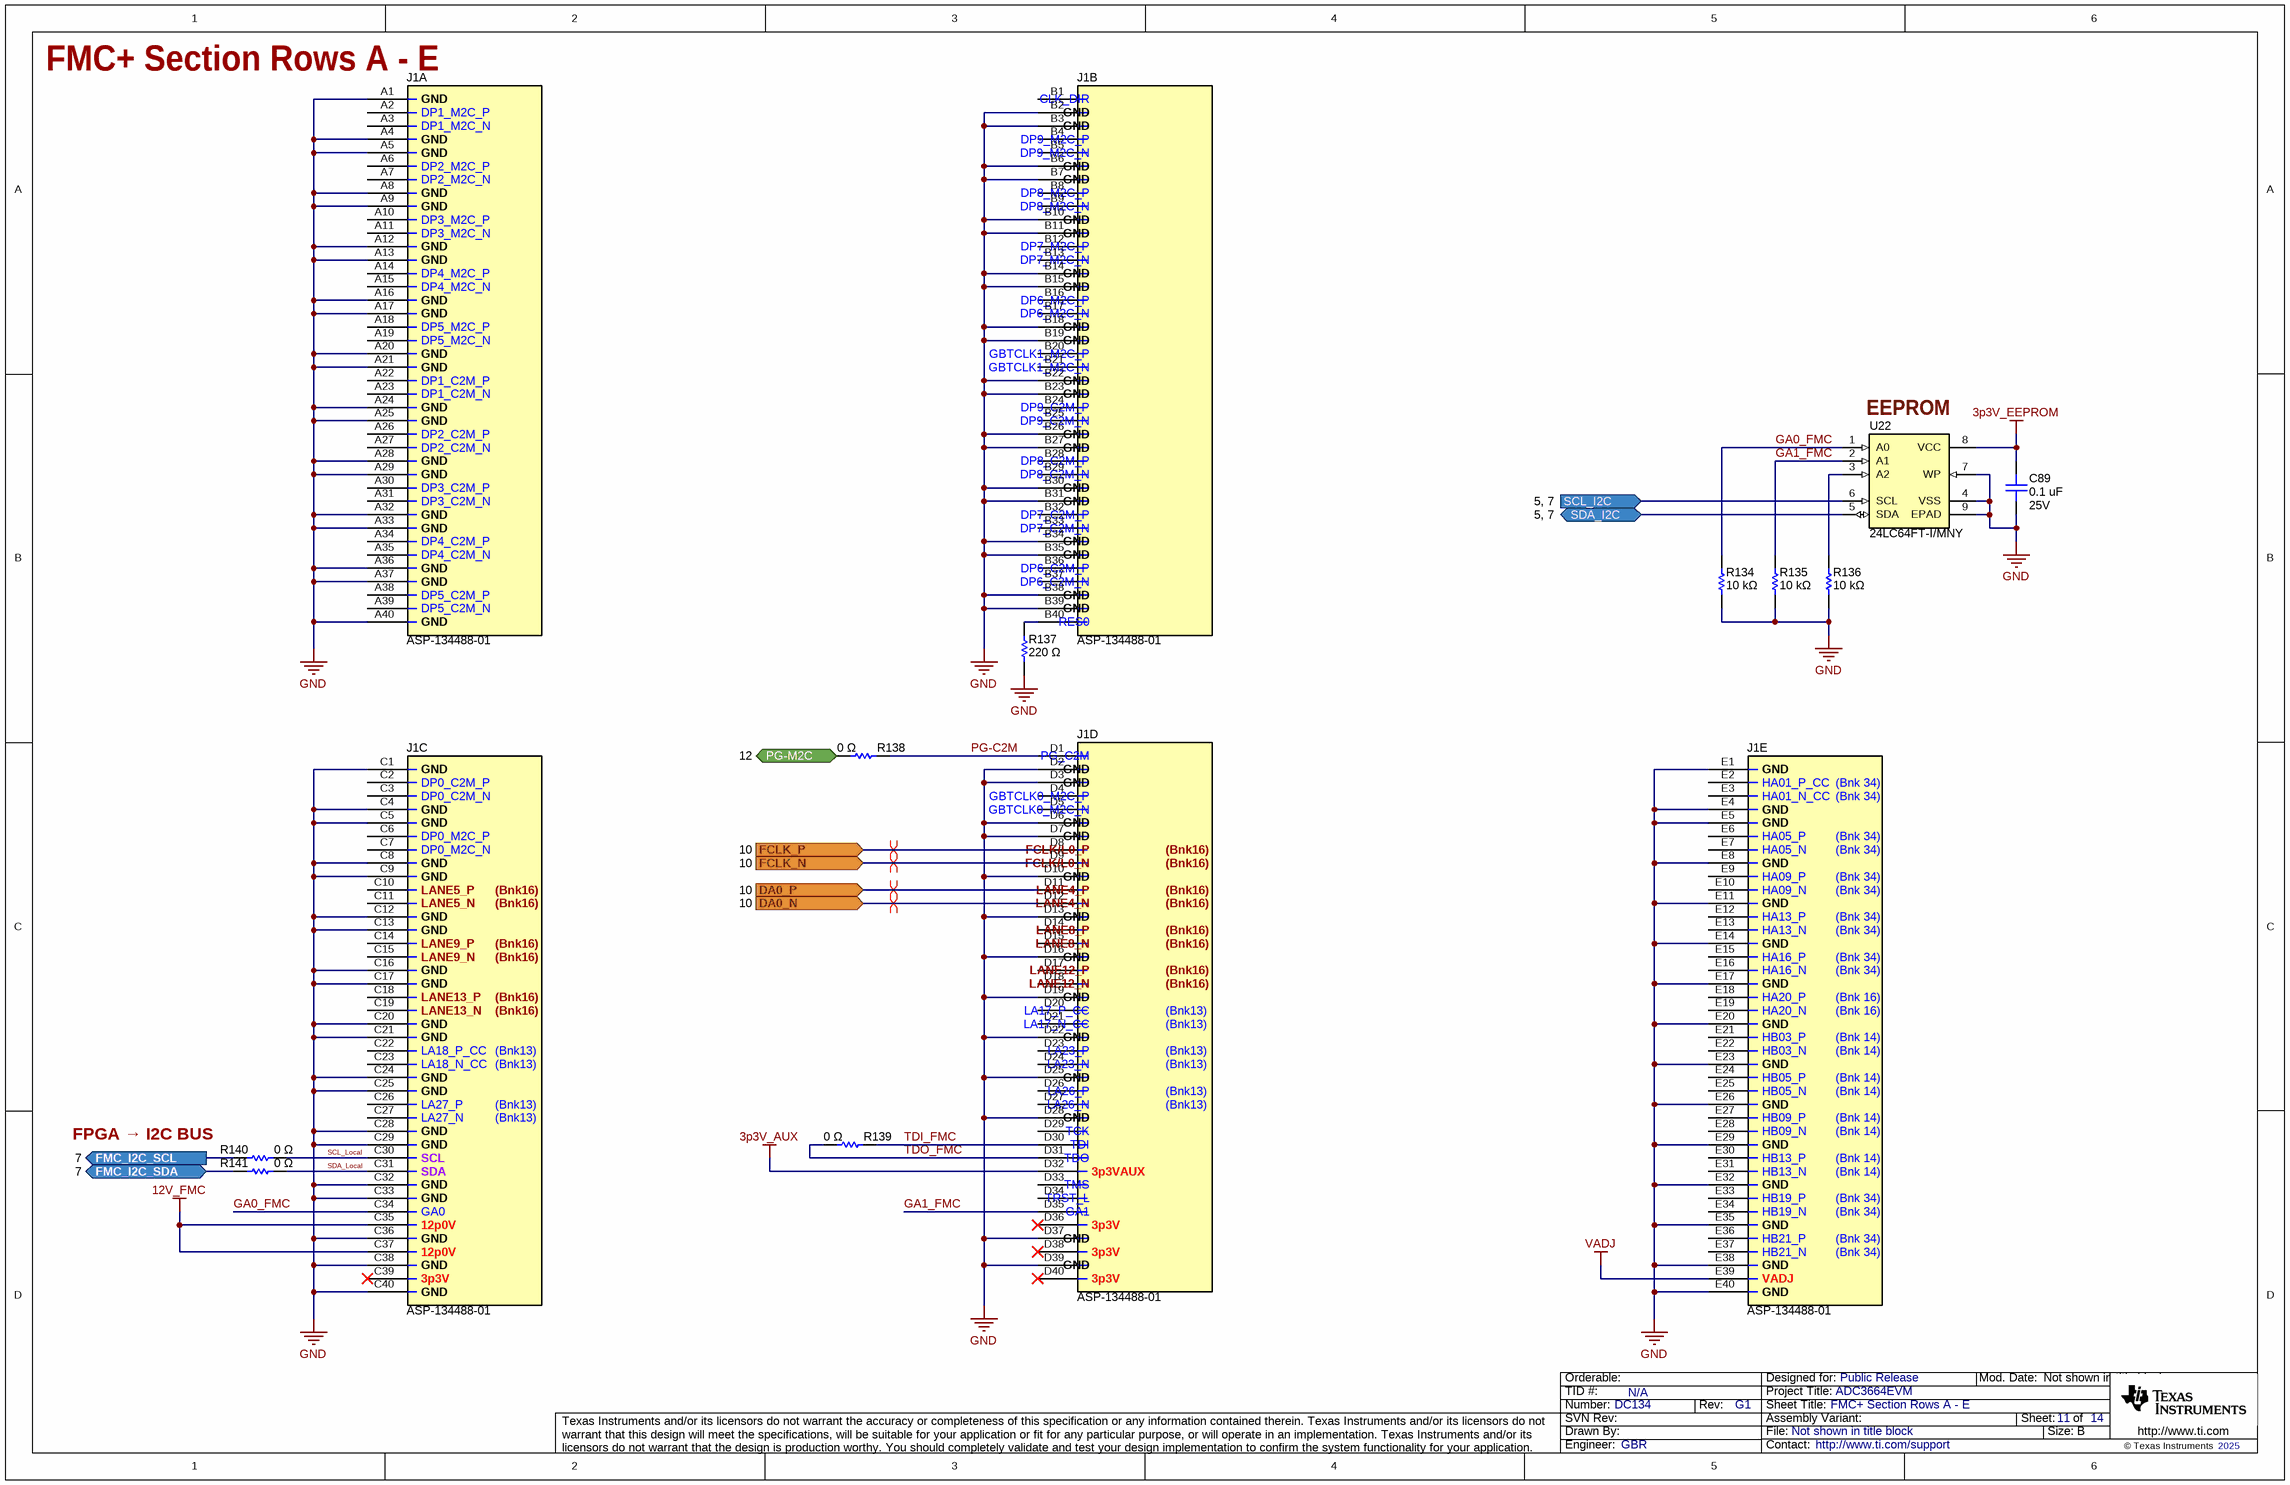
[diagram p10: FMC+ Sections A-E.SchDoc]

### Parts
C89  value 0.1 uF  Voltage - Rated: 25V  [0402L_cap]  (hidden comment: GRT155R71E104KE01J)
J1  ASP-134488-01  [SAMTEC_ASP-134488-01]  (parts A,B,C,D,E of 10)
R134  value 10 kΩ  [0201]  (hidden comment: ERJ-1GNJ103C)
R135  value 10 kΩ  [0201]  (hidden comment: ERJ-1GNJ103C)
R136  value 10 kΩ  [0201]  (hidden comment: ERJ-1GNJ103C)
R137  value 220 Ω  [0201]  (hidden comment: ERJ-1GNF2200C)
R138  value 0 Ω  [0201]  (hidden comment: ERJ-1GN0R00C)
R139  value 0 Ω  [0201]  (hidden comment: ERJ-1GN0R00C)
R140  value 0 Ω  [0201]  (hidden comment: ERJ-1GN0R00C)
R141  value 0 Ω  [0201]  (hidden comment: ERJ-1GN0R00C)
U22  24LC64FT-I/MNY  [TDFN8]

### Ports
DA0_N (in, see 10), DA0_P (in, see 10), FCLK_N (in, see 10), FCLK_P (in, see 10), FMC_I2C_SCL (out, see 7), FMC_I2C_SDA (bidir, see 7), PG-M2C (bidir, see 12), SCL_I2C (in, see 5, 7), SDA_I2C (bidir, see 5, 7)

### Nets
3p3V_AUX: J1.D32
3p3V_EEPROM: C89.2 U22.8(VCC)
12V_FMC: J1.C35 J1.C37
GND: C89.1 J1.A1 J1.A4 J1.A5 J1.A8 J1.A9 J1.A12 J1.A13 J1.A16 J1.A17 J1.A20 J1.A21 J1.A24 J1.A25 J1.A28 J1.A29 J1.A32 J1.A33 J1.A36 J1.A37 J1.A40 J1.B2 J1.B3 J1.B6 J1.B7 J1.B10 J1.B11 J1.B14 J1.B15 J1.B18 J1.B19 J1.B22 J1.B23 J1.B26 J1.B27 J1.B30 J1.B31 J1.B34 J1.B35 J1.B38 J1.B39 J1.C1 J1.C4 J1.C5 J1.C8 J1.C9 J1.C12 J1.C13 J1.C16 J1.C17 J1.C20 J1.C21 J1.C24 J1.C25 J1.C28 J1.C29 J1.C32 J1.C33 J1.C36 J1.C38 J1.C40 J1.D2 J1.D3 J1.D6 J1.D7 J1.D10 J1.D13 J1.D16 J1.D19 J1.D22 J1.D25 J1.D28 J1.D37 J1.D39 J1.E1 J1.E4 J1.E5 J1.E8 J1.E11 J1.E14 J1.E17 J1.E20 J1.E23 J1.E26 J1.E29 J1.E32 J1.E35 J1.E38 J1.E40 R134.1 R135.1 R136.1 R137.1 U22.4(VSS) U22.7(WP) U22.9(EPAD)
VADJ: J1.E39
DA0_N: J1.D12 ; port DA0_N
DA0_P: J1.D11 ; port DA0_P
FCLK_N: J1.D9 ; port FCLK_N
FCLK_P: J1.D8 ; port FCLK_P
FMC_I2C_SCL: R140.1 ; port FMC_I2C_SCL
FMC_I2C_SDA: R141.1 ; port FMC_I2C_SDA
GA0_FMC: J1.C34 R134.2 U22.1(A0)
GA1_FMC: J1.D35 R135.2 U22.2(A1)
PG-C2M: J1.D1 R138.2
PG-M2C: R138.1 ; port PG-M2C
SCL_I2C: U22.6(SCL) ; port SCL_I2C
SCL_Local: J1.C30 R140.2
SDA_I2C: U22.5(SDA) ; port SDA_I2C
SDA_Local: J1.C31 R141.2
TDI_FMC: J1.D30 R139.2
TDO_FMC: J1.D31 R139.1
NetJ1_B40: J1.B40 R137.2
NetR136_2: R136.2 U22.3(A2)

Not connected (* = marked no-connect by the designer): J1 A2 A3 A6 A7 A10 A11 A14 A15 A18 A19 A22 A23 A26 A27 A30 A31 A34 A35 A38 A39 B1 B4 B5 B8 B9 B12 B13 B16 B17 B20 B21 B24 B25 B28 B29 B32 B33 B36 B37 C2 C3 C6 C7 C10 C11 C14 C15 C18 C19 C22 C23 C26 C27 C39* D4 D5 D14 D15 D17 D18 D20 D21 D23 D24 D26 D27 D29 D33 D34 D36* D38* D40* E2 E3 E6 E7 E9 E10 E12 E13 E15 E16 E18 E19 E21 E22 E24 E25 E27 E28 E30 E31 E33 E34 E36 E37

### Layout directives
differential pair; net class DiffPair: DA0_N, DA0_P, FCLK_N, FCLK_P

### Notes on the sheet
- (near U22) EEPROM
- FPGA → I2C BUS

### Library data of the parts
C89 = capcc09401: as C81 on sheet DUT IO
J1 = ASP-134488-01: FMC, High Density Array, Male / EVM Connector 40x10; Manufacturer: Samtec; UniqueID: cmp00010; Pitch (mm): 1.27
R134-R136 = RSMD020101186: RES SMD 10K OHM 5% 1/20W 0201; Manufacturer: Panasonic Electronic Components; CompType: Resistor SMD; Power (Watts): 0.05W, 1/20W; Temperature Coefficient: ±200ppm/°C
R137 = RSMD020100147: RES SMD 220 OHM 1% 1/20W 0201; Manufacturer: Panasonic Electronic Components; CompType: Resistor SMD; Power (Watts): 0.05W, 1/20W; Temperature Coefficient: ±200ppm/°C
R138-R141 = RSMD020101699: as R76 on sheet ADC Inputs
U22 = cmp00154: EEPROM 64K 8KX8 1.8V SER EE IND 1/4AWP RPO; Manufacturer: Microchip

## Sheet FMC+ Sections F-H, J, K.SchDoc: FMC+ Section Rows F - H, J, K
size 431 x 279 mm; Date: Not shown in title block; ApprovedBy: Not shown in title block; CheckedBy: Not shown in title block; Author: Not shown in title block; CompanyName: Not shown in title block; Engineer: Not shown in title block; Organization: Not shown in title block; Address1: Not shown in title block; Address2: Not shown in title block; Address3: Not shown in title block; Address4: Not shown in title block; DocumentNumber: 3; Revision: Use project parameter SCH_Rev; SheetNumber: 12; SheetTotal: 14; PageSetup: Record=PageOptions¦CenterHorizontal=True¦CenterVertical=True¦PrintScale=1.00¦XCorrection=1.00¦YCorrection=1.00¦PrintKind=0¦BorderSize=5000000¦LeftOffset=0¦BottomOffset=0¦Orientation=2¦PaperLength=1000¦PaperWidth=1000¦Scale=100¦PaperSource=15¦PrintQuality=600¦MediaType=1¦DitherType=10¦PaperKind=Letter¦PrintScaleMode=1
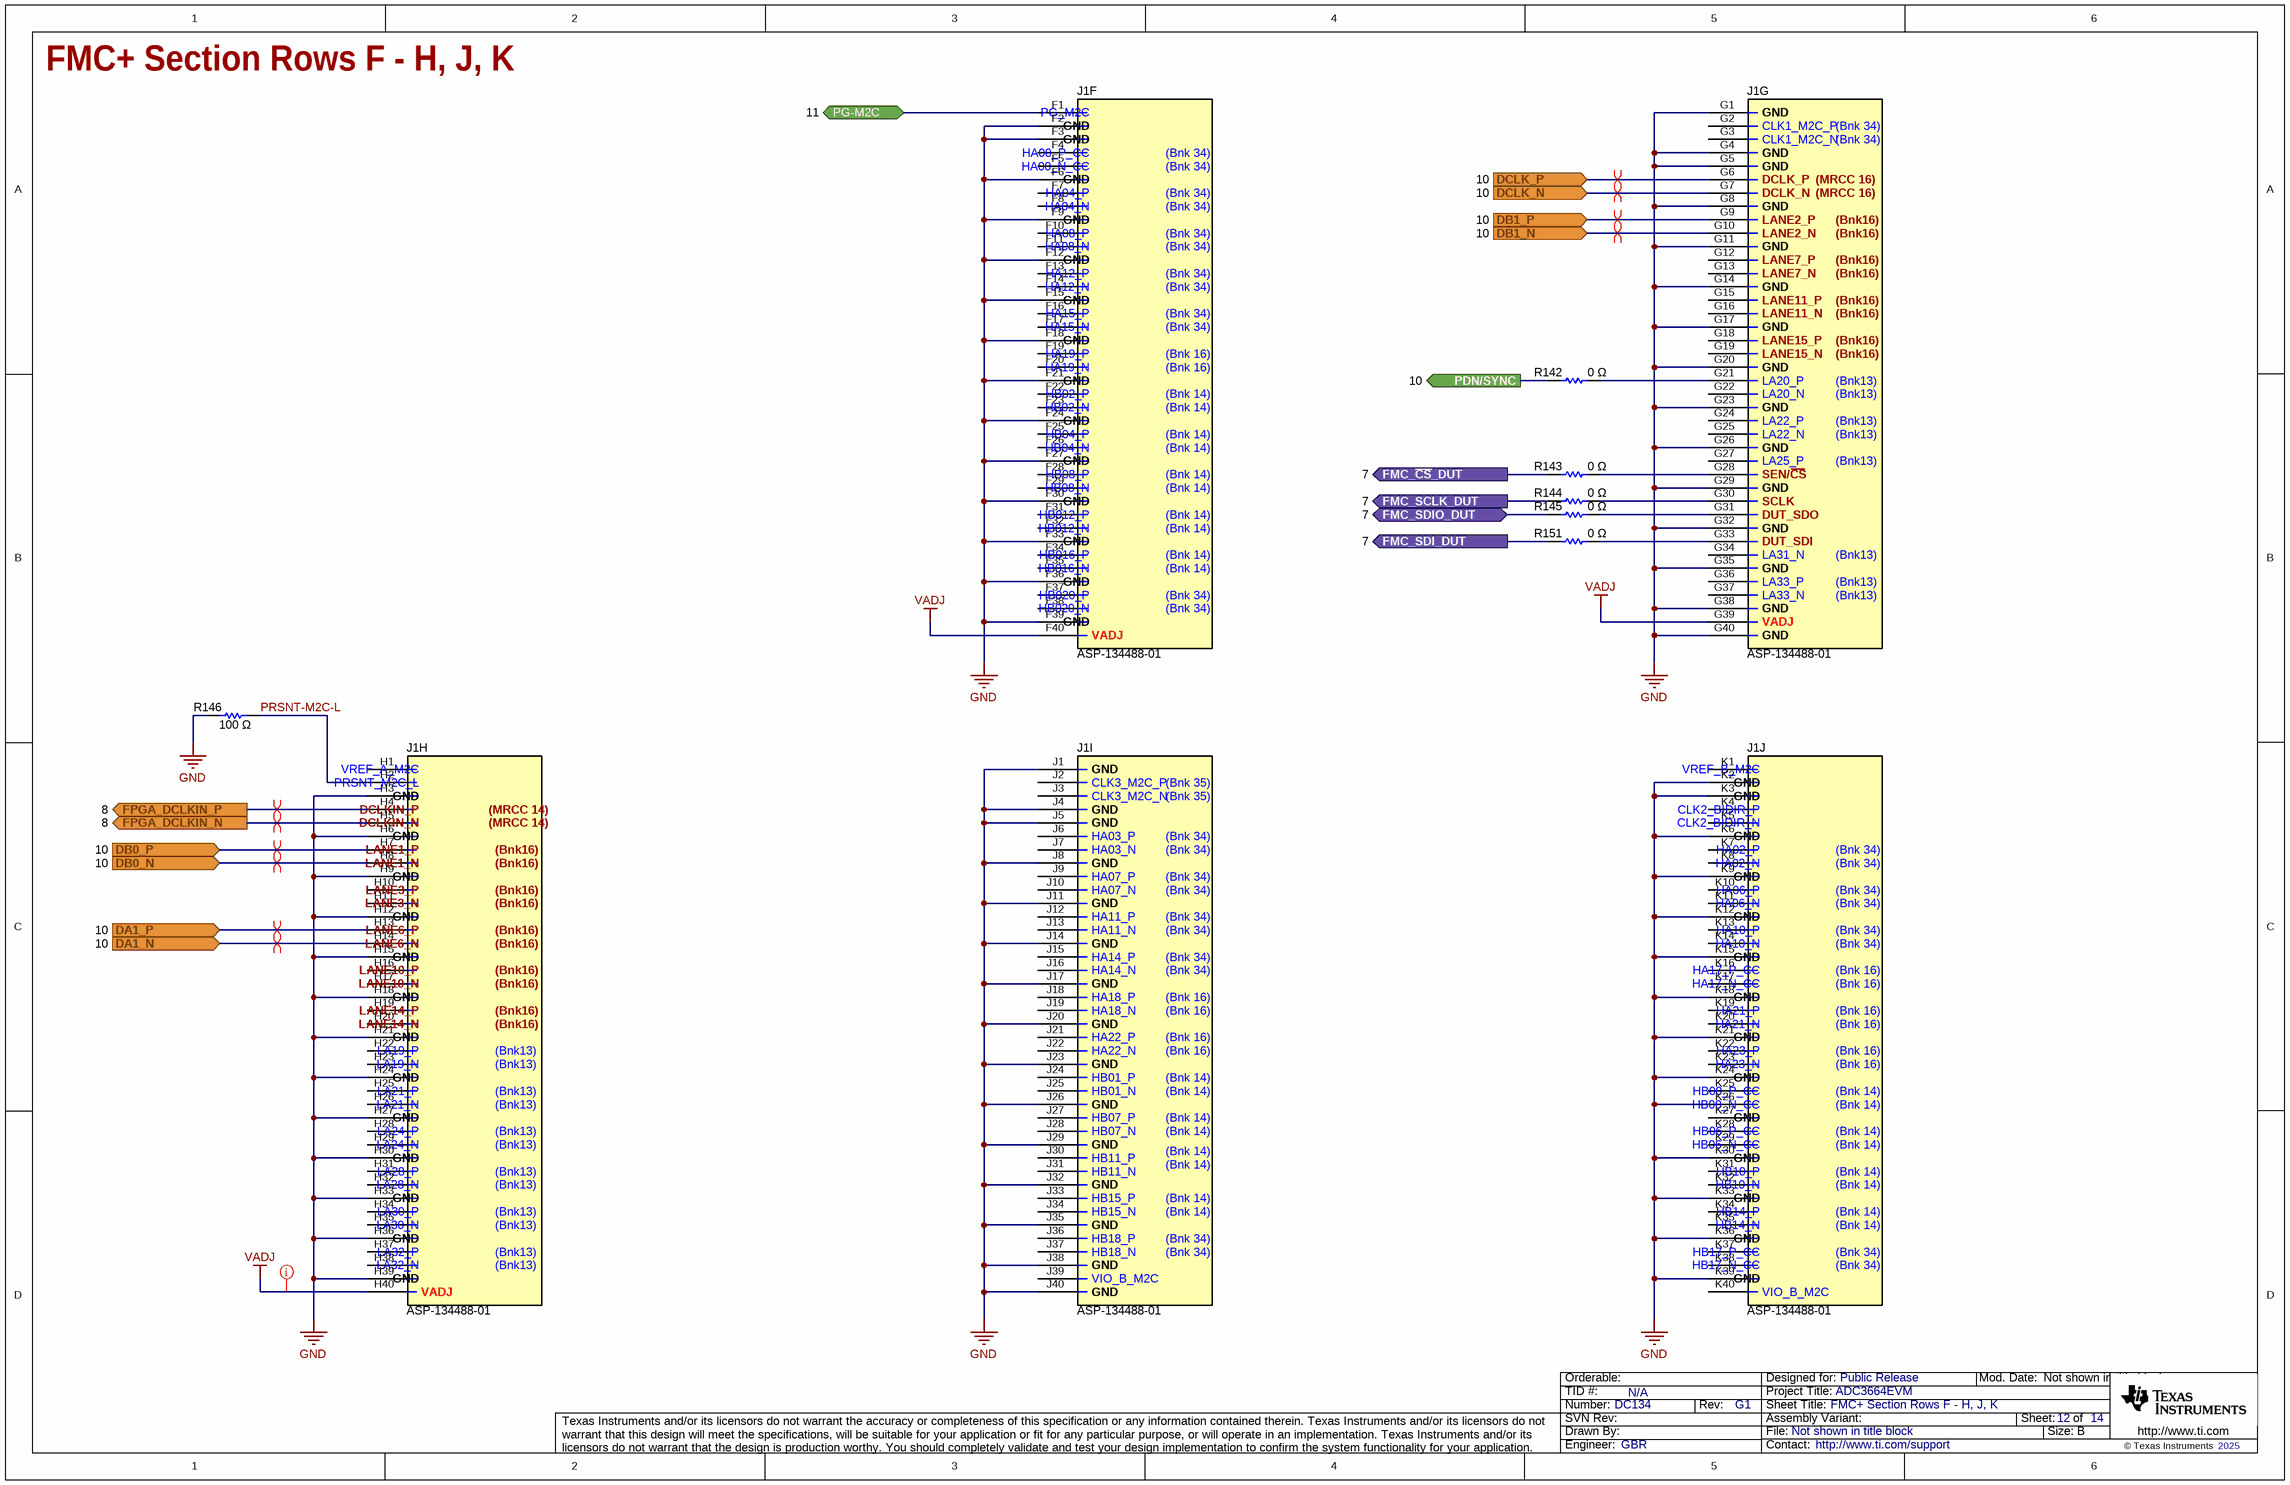
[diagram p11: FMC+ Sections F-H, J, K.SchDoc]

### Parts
J1  ASP-134488-01  [SAMTEC_ASP-134488-01]  (parts F,G,H,I,J of 10)
R142  value 0 Ω  [0201]  (hidden comment: ERJ-1GN0R00C)
R143  value 0 Ω  [0201]  (hidden comment: ERJ-1GN0R00C)
R144  value 0 Ω  [0201]  (hidden comment: ERJ-1GN0R00C)
R145  value 0 Ω  [0201]  (hidden comment: ERJ-1GN0R00C)
R146  value 100 Ω  [0402L]  (hidden comment: ERJ-2RKF1000X)
R151  value 0 Ω  [0201]  (hidden comment: ERJ-1GN0R00C)

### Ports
DA1_N (in, see 10), DA1_P (in, see 10), DB0_N (in, see 10), DB0_P (in, see 10), DB1_N (in, see 10), DB1_P (in, see 10), DCLK_N (in, see 10), DCLK_P (in, see 10), FMC_SCLK_DUT (out, see 7), FMC_SDI_DUT (out, see 7), FMC_SDIO_DUT (bidir, see 7), FMC_~{CS}_DUT (out, see 7), FPGA_DCLKIN_N (out, see 8), FPGA_DCLKIN_P (out, see 8), PDN/SYNC (out, see 10), PG-M2C (bidir, see 11)

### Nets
GND: J1.F2 J1.F3 J1.F6 J1.F9 J1.F12 J1.F15 J1.F18 J1.F21 J1.F24 J1.F27 J1.F30 J1.F33 J1.F36 J1.F39 J1.G1 J1.G4 J1.G5 J1.G8 J1.G11 J1.G14 J1.G17 J1.G20 J1.G23 J1.G26 J1.G29 J1.G32 J1.G35 J1.G38 J1.G40 J1.H3 J1.H6 J1.H9 J1.H12 J1.H15 J1.H18 J1.H21 J1.H24 J1.H27 J1.H30 J1.H33 J1.H36 J1.H39 J1.J1 J1.J4 J1.J5 J1.J8 J1.J11 J1.J14 J1.J17 J1.J20 J1.J23 J1.J26 J1.J29 J1.J32 J1.J35 J1.J38 J1.J40 J1.K2 J1.K3 J1.K6 J1.K9 J1.K12 J1.K15 J1.K18 J1.K21 J1.K24 J1.K26 J1.K30 J1.K33 J1.K36 J1.K39 R146.1
VADJ: J1.F40 J1.G39 J1.H40
DA1_N: J1.H14 ; port DA1_N
DA1_P: J1.H13 ; port DA1_P
DB0_N: J1.H8 ; port DB0_N
DB0_P: J1.H7 ; port DB0_P
DB1_N: J1.G10 ; port DB1_N
DB1_P: J1.G9 ; port DB1_P
DCLK_N: J1.G7 ; port DCLK_N
DCLK_P: J1.G6 ; port DCLK_P
FMC_~{CS}_DUT_LVLS: R143.1 ; port FMC_~{CS}_DUT
FMC_SCLK_DUT_LVLS: R144.1 ; port FMC_SCLK_DUT
FMC_SDI_DUT: R151.1 ; port FMC_SDI_DUT
FMC_SDIO_DUT_LVLS: R145.1 ; port FMC_SDIO_DUT
FPGA_DCLKIN_N: J1.H5 ; port FPGA_DCLKIN_N
FPGA_DCLKIN_P: J1.H4 ; port FPGA_DCLKIN_P
PDN/SYNC: R142.1 ; port PDN/SYNC
PG-M2C: J1.F1 ; port PG-M2C
PRSNT-M2C-L: J1.H2 R146.2
NetJ1_G21: J1.G21 R142.2
NetJ1_G28: J1.G28 R143.2
NetJ1_G30: J1.G30 R144.2
NetJ1_G31: J1.G31 R145.2
NetJ1_G33: J1.G33 R151.2

Not connected (* = marked no-connect by the designer): J1 F4 F5 F7 F8 F10 F11 F13 F14 F16 F17 F19 F20 F22 F23 F25 F26 F28 F29 F31 F32 F34 F35 F37 F38 G2 G3 G12 G13 G15 G16 G18 G19 G22 G24 G25 G27 G34 G36 G37 H1 H10 H11 H16 H17 H19 H20 H22 H23 H25 H26 H28 H29 H31 H32 H34 H35 H37 H38 J2 J3 J6 J7 J9 J10 J12 J13 J15 J16 J18 J19 J21 J22 J24 J25 J27 J28 J30 J31 J33 J34 J36 J37 J39 K1 K4 K5 K7 K8 K10 K11 K13 K14 K16 K17 K19 K20 K22 K23 K25 K27 K28 K29 K31 K32 K34 K35 K37 K38 K40

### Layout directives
net class Power; net class FMCPwr: VADJ
differential pair; net class DiffPair: DA1_N, DA1_P, DB0_N, DB0_P, DB1_N, DB1_P, DCLK_N, DCLK_P
differential pair: FPGA_DCLKIN_N, FPGA_DCLKIN_P

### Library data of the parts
J1 = ASP-134488-01: as J1 on sheet FMC+ Sections A-E
R142-R145 R151 = RSMD020101699: as R76 on sheet ADC Inputs
R146 = RSMD040200375: RES SMD 100 OHM 1% 1/10W 0402; Manufacturer: Panasonic Electronic Components; CompType: Resistor SMD; Power (Watts): 0.1W, 1/10W; Temperature Coefficient: ±100ppm/°C; SizeX_mm: 1; SizeY_mm: 0.5; SizeZ_mm: 0.4

## Sheet Hardware & Mechanicals.SchDoc: Hardware & Mechanicals
size 431 x 279 mm; Date: Not shown in title block; ApprovedBy: Not shown in title block; CheckedBy: Not shown in title block; Author: Not shown in title block; CompanyName: Not shown in title block; Engineer: Not shown in title block; Organization: Not shown in title block; Address1: Not shown in title block; Address2: Not shown in title block; Address3: Not shown in title block; Address4: Not shown in title block; DocumentNumber: 4; Revision: Use project parameter SCH_Rev; SheetNumber: 13; SheetTotal: 14; PageSetup: Record=PageOptions¦CenterHorizontal=True¦CenterVertical=True¦PrintScale=1.00¦XCorrection=1.00¦YCorrection=1.00¦PrintKind=0¦BorderSize=5000000¦LeftOffset=0¦BottomOffset=0¦Orientation=2¦PaperLength=1000¦PaperWidth=1000¦Scale=100¦PaperSource=15¦PrintQuality=600¦MediaType=1¦DitherType=10¦PaperKind=Letter¦PrintScaleMode=1
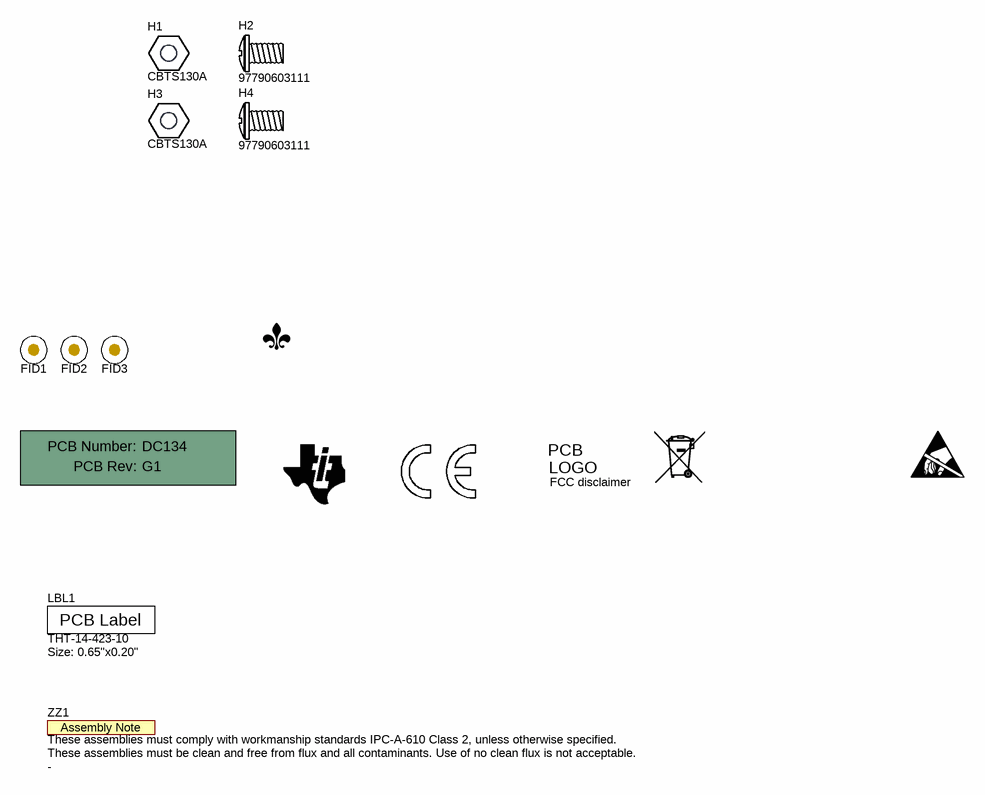
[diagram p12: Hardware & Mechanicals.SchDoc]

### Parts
!PCB1  (no value)  (mechanical)
FID1  Fiducial Mark  [Fiducial10-20]  (value not drawn)  (no BOM)
FID2  Fiducial Mark  [Fiducial10-20]  (value not drawn)  (no BOM)
FID3  Fiducial Mark  [Fiducial10-20]  (value not drawn)  (no BOM)
H1  CBTS130A  [cbts130a]
H2  97790603111  [97790603111]  (mechanical)
H3  CBTS130A  [cbts130a]
H4  97790603111  [97790603111]  (mechanical)
LBL1  THT-14-423-10  Text1: Size: 0.65"x0.20"  [Label_650x200]
Logo1  FDL Logo  [FDL_Small]  (value not drawn)  (no BOM)
Logo2  FCC disclaimer  [FCC_disclaimer]  (no BOM)
Logo3  ESD Overlay  [ESD_Overlay_Small]  (value not drawn)  (no BOM)
Logo4  WEEE  [WEEE_Minimum]  (value not drawn)  (no BOM)
LOGO5  CE Mark  [CE_Mark_5mm]  (value not drawn)  (no BOM)
Logo6  Texas Instruments  [TI_Stacked_Overlay_Small_Vertical]  (value not drawn)  (no BOM)
ZZ1  Text3: These assemblies must comply with workmanship standards IPC-A-610 Class 2, unless otherwise specified.  Text2: These assemblies must be clean and free from flux and all contaminants. Use of no clean flux is not acceptable.  [AssemblyNote]  (hidden comment: These assemblies are ESD sensitive, ESD precautions shall be observed.)  (no BOM)

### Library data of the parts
!PCB1 = cmp00109: Printed Circuit Board; CompType: PCB
FID1-FID3 = cmp00099: Fiducial; SymbolCreator: a0412235
H1 H3 = CBTS130A: Hex Standoff Threaded M3 Nylon 1.260" (32.00mm) Natural; Manufacturer: Essentra Components; UniqueID: CBTS010A
H2 H4 = 97790603111: M3 Pan Head Machine Screw Phillips Drive Nylon; Manufacturer: Murth Elektronik
LBL1 = cmp00106: Thermal Transfer Printable Labels, 0.650" W x 0.200" H - 10,000 per roll; Manufacturer: Brady; CompType: Label
Logo1 = cmp00105: FDL
Logo2 = cmp00102: FCC_disclaimer; CompType: Logo
Logo3 = cmp00317: PartNumber: ESD Logo; CompType: Logo
Logo4 = cmp00101: CompType: Logo
LOGO5 = cmp00103: CE_Mark; CompType: Logo
Logo6 = cmp00104: Texas Instrument Corporate Signature; PartNumber: TI Bug; CompType: Logo
ZZ1 = cmp00108: Assembly Notes

## Sheet Revision History.SchDoc: Rev History & Variants
size 431 x 279 mm; Date: Not shown in title block; ApprovedBy: Not shown in title block; CheckedBy: Not shown in title block; Author: Not shown in title block; CompanyName: Not shown in title block; Engineer: Not shown in title block; Organization: Not shown in title block; Address1: Not shown in title block; Address2: Not shown in title block; Address3: Not shown in title block; Address4: Not shown in title block; DocumentNumber: 5; Revision: Use project parameter SCH_Rev; SheetNumber: 14; SheetTotal: 14; PageSetup: Record=PageOptions¦CenterHorizontal=True¦CenterVertical=True¦PrintScale=1.00¦XCorrection=1.00¦YCorrection=1.00¦PrintKind=0¦BorderSize=5000000¦LeftOffset=0¦BottomOffset=0¦Orientation=2¦PaperLength=1000¦PaperWidth=1000¦Scale=100¦PaperSource=15¦PrintQuality=600¦MediaType=1¦DitherType=10¦PaperKind=Letter¦PrintScaleMode=1
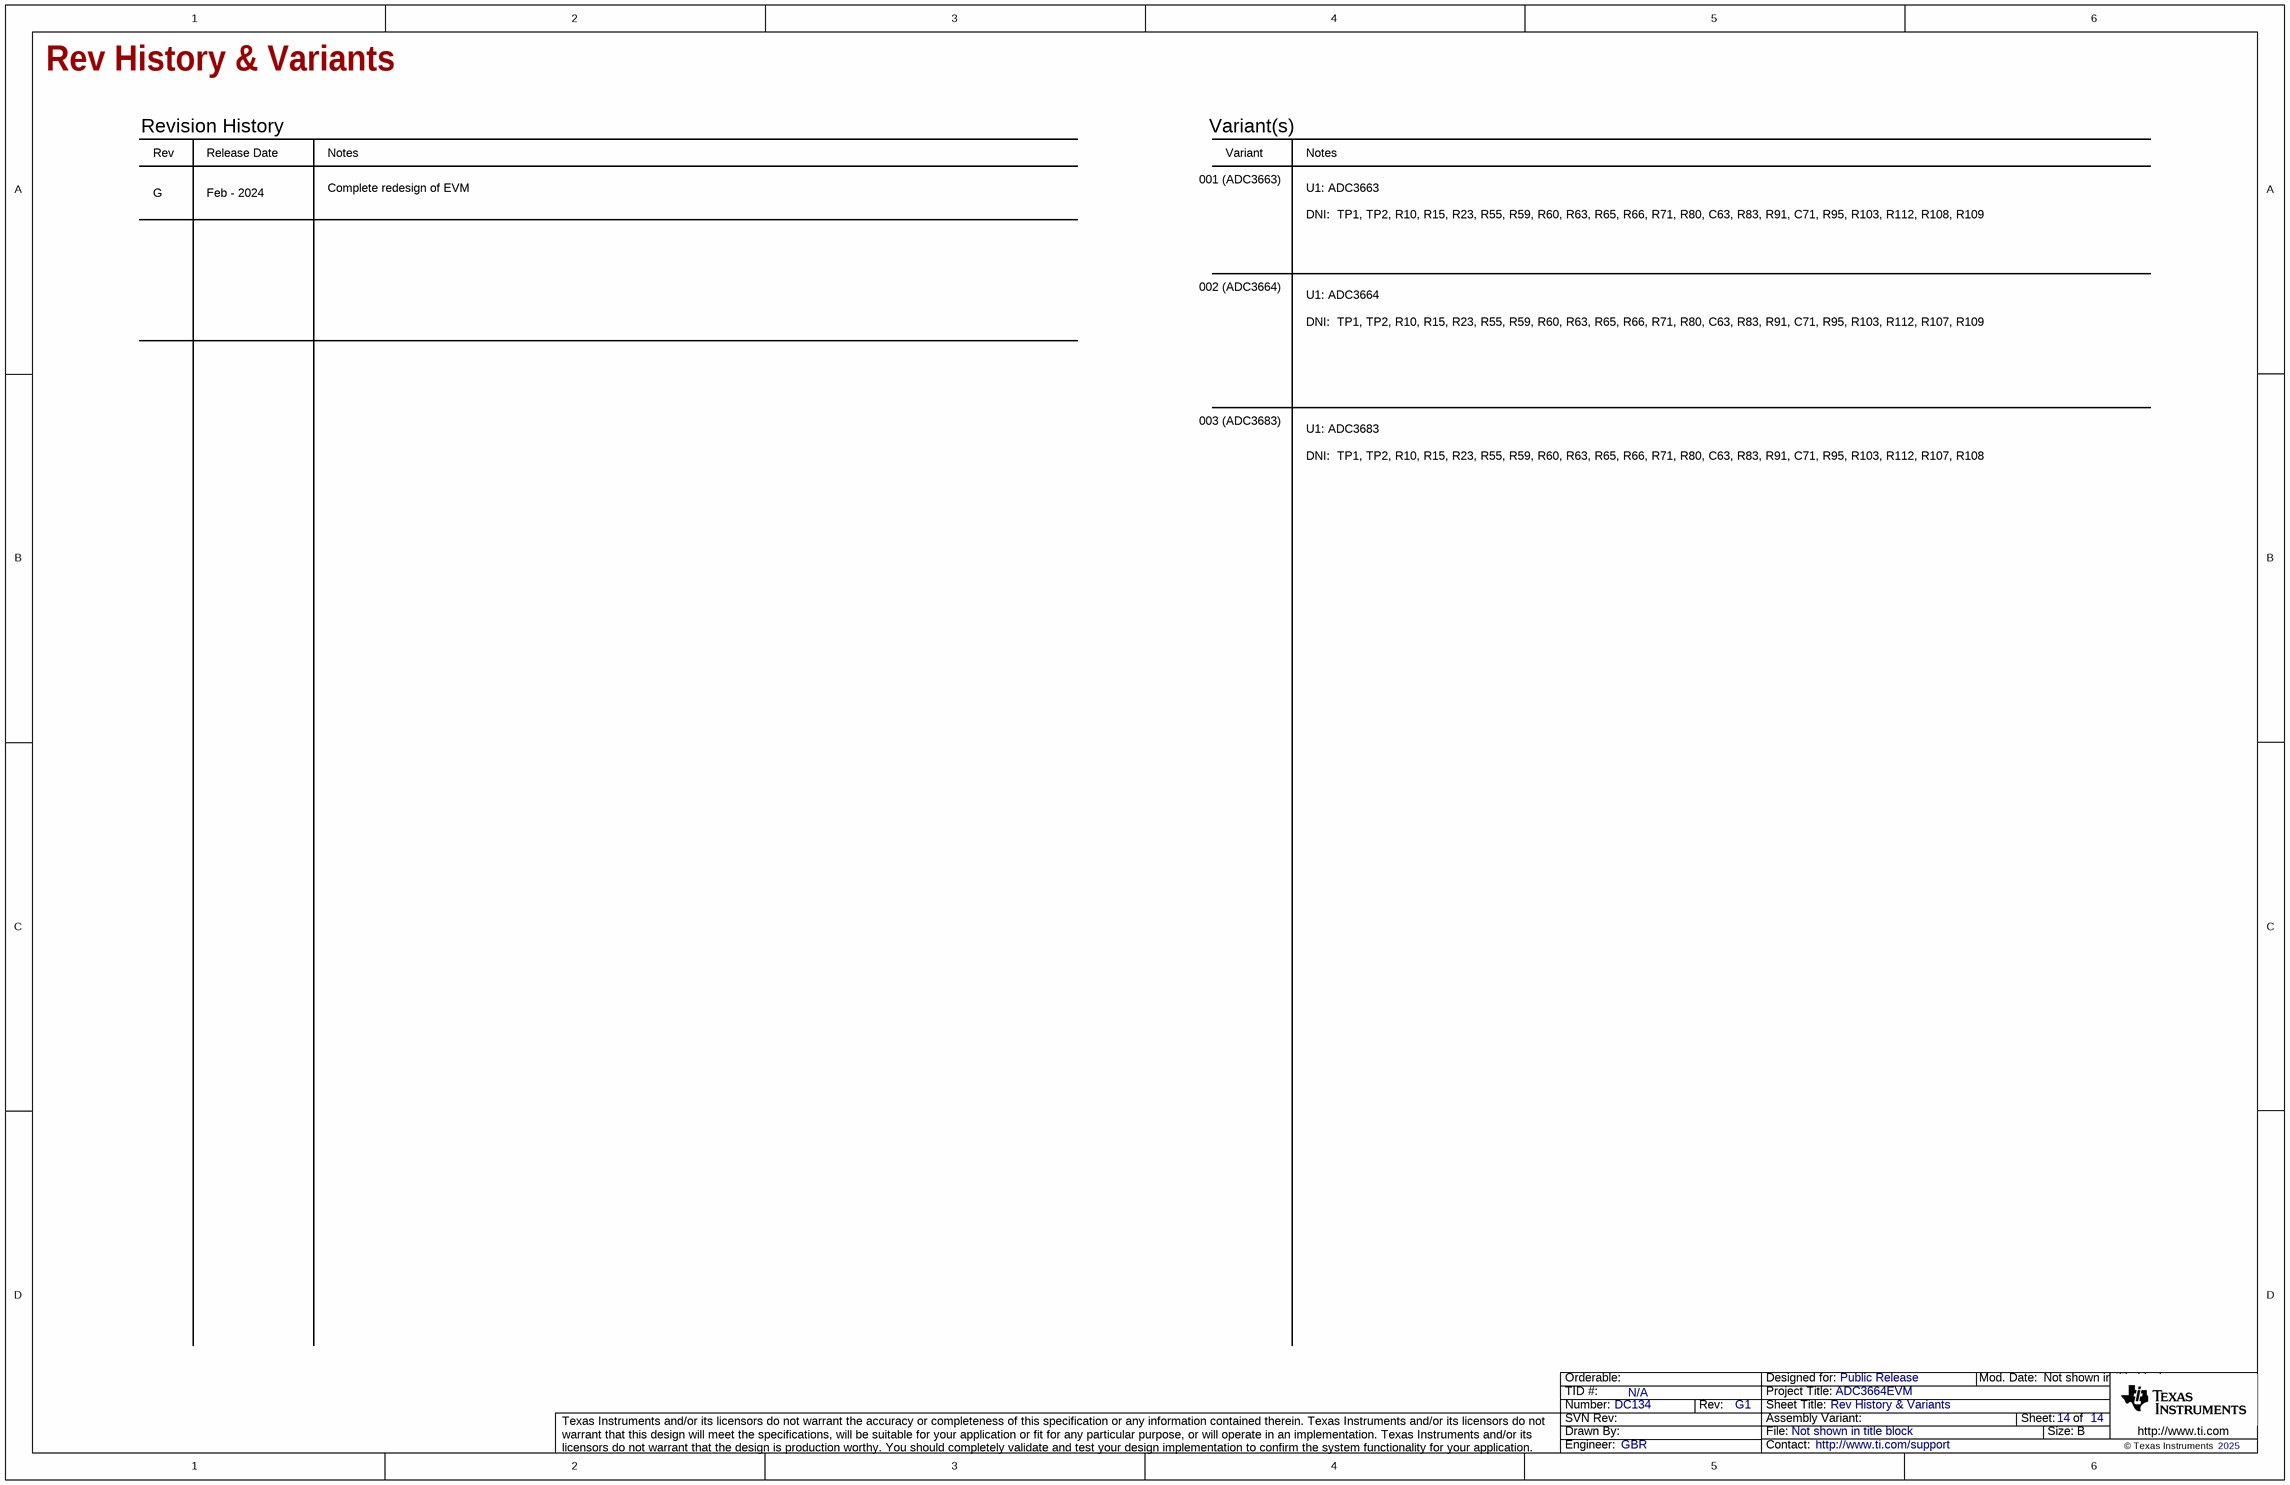
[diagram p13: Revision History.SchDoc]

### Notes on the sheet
- Rev
- Release Date
- Revision History
- Notes
- Variant
- Variant(s)
- G
- Feb - 2024
- Complete redesign of EVM
- 001 (ADC3663)
- 002 (ADC3664)
- U1: ADC3663
  DNI:  TP1, TP2, R10, R15, R23, R55, R59, R60, R63, R65, R66, R71, R80, C63, R83, R91, C71, R95, R103, R112, R108, R109
- U1: ADC3664
  DNI:  TP1, TP2, R10, R15, R23, R55, R59, R60, R63, R65, R66, R71, R80, C63, R83, R91, C71, R95, R103, R112, R107, R109
- 003 (ADC3683)
- U1: ADC3683
  DNI:  TP1, TP2, R10, R15, R23, R55, R59, R60, R63, R65, R66, R71, R80, C63, R83, R91, C71, R95, R103, R112, R107, R108

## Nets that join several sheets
1p8V_AVDD: Power LDO (C21.2 FB2.2 PP3.1), Power Sense ADC (U9.8), DUT IO (6 pins)
1p8V_IOVDD: Power LDO (C27.2 FB3.2 PP4.1), Power Sense ADC (U9.4), DUT IO (C77.2 C78.2 U1.21 U1.30)
1p8V_LVLSHIFT: Power LDO (6 pins), Comms LVL Shift and MUX (9 pins), DUT IO (7 pins)
2p3V: Power DC-DC (5 pins), Power LDO (10 pins)
3p3V_Utility: 12V Input, Efuse and 3p3V Utility (6 pins), Power DC-DC (R10.2), Power LDO (6 pins), Power Sense ADC (6 pins), USB Control FTDI (24 pins), Comms LVL Shift and MUX (13 pins), CLK and DCLKIN (7 pins), DUT IO (C86.2 R131.2 U21.4)
12V: 12V Input, Efuse and 3p3V Utility (10 pins), Power DC-DC (C9.2 C10.2 R11.2 U4.18), Power LDO (D4.1 D5.1)
12V_FMC: 12V Input, Efuse and 3p3V Utility (SW1.3), FMC+ Sections A-E (J1.C35 J1.C37)
GND: 12V Input, Efuse and 3p3V Utility (16 pins), Power DC-DC (24 pins), Power LDO (24 pins), Power Sense ADC (7 pins), USB Control FTDI (32 pins), Comms LVL Shift and MUX (20 pins), CLK and DCLKIN (26 pins), ADC Inputs (24 pins), DUT IO (35 pins), FMC+ Sections A-E (96 pins), FMC+ Sections F-H, J, K (72 pins)
VADJ: FMC+ Sections A-E (J1.E39), FMC+ Sections F-H, J, K (J1.F40 J1.G39 J1.H40)
VCM: ADC Inputs (6 pins), DUT IO (C79.2 C80.2 TP3.1 U1.8)
3p3VU_PG: 12V Input, Efuse and 3p3V Utility (R5.1 U3.7), Power DC-DC (R9.2)
AIN_N: ADC Inputs (R87.2), DUT IO (U1.13)
AIN_P: ADC Inputs (R79.2), DUT IO (U1.12)
BIN_N: ADC Inputs (R91.2), DUT IO (U1.38)
BIN_P: ADC Inputs (R99.2), DUT IO (U1.39)
CLK_N: CLK and DCLKIN (C54.2 R65.1), DUT IO (U1.7)
CLK_P: CLK and DCLKIN (C48.2 R65.2), DUT IO (U1.6)
DA0_N: DUT IO (R113.2), FMC+ Sections A-E (J1.D12)
DA0_P: DUT IO (R112.2), FMC+ Sections A-E (J1.D11)
DA1_N: DUT IO (R115.2), FMC+ Sections F-H, J, K (J1.H14)
DA1_P: DUT IO (R114.2), FMC+ Sections F-H, J, K (J1.H13)
DB0_N: DUT IO (R117.2), FMC+ Sections F-H, J, K (J1.H8)
DB0_P: DUT IO (R116.2), FMC+ Sections F-H, J, K (J1.H7)
DB1_N: DUT IO (R119.2), FMC+ Sections F-H, J, K (J1.G10)
DB1_P: DUT IO (R118.2), FMC+ Sections F-H, J, K (J1.G9)
DC-DC_PG: Power DC-DC (R10.1 U4.19), Power LDO (R23.2)
DCLK_N: DUT IO (R108.2), FMC+ Sections F-H, J, K (J1.G7)
DCLK_P: DUT IO (R107.2), FMC+ Sections F-H, J, K (J1.G6)
DCLKIN_N: CLK and DCLKIN (R72.2), DUT IO (R104.2)
DCLKIN_P: CLK and DCLKIN (R71.2), DUT IO (R105.2)
FCLK_N: DUT IO (R110.2), FMC+ Sections A-E (J1.D9)
FCLK_P: DUT IO (R109.2), FMC+ Sections A-E (J1.D8)
FMC_~{CS}_DUT_LVLS: Comms LVL Shift and MUX (R60.1 U15.4), FMC+ Sections F-H, J, K (R143.1)
FMC_I2C_SCL: Comms LVL Shift and MUX (U13.4), FMC+ Sections A-E (R140.1)
FMC_I2C_SDA: Comms LVL Shift and MUX (U13.2), FMC+ Sections A-E (R141.1)
FMC_SCLK_DUT_LVLS: Comms LVL Shift and MUX (R59.1 U15.1), FMC+ Sections F-H, J, K (R144.1)
FMC_SDI_DUT: Comms LVL Shift and MUX (R147.2 U23.1), FMC+ Sections F-H, J, K (R151.1)
FMC_SDIO_DUT_LVLS: Comms LVL Shift and MUX (5 pins), FMC+ Sections F-H, J, K (R145.1)
FPGA_DCLKIN_N: CLK and DCLKIN (U17.4), FMC+ Sections F-H, J, K (J1.H5)
FPGA_DCLKIN_P: CLK and DCLKIN (U17.3), FMC+ Sections F-H, J, K (J1.H4)
FTDI_CSb_SHIFT: USB Control FTDI (U11.17), Comms LVL Shift and MUX (R53.1 U14.4)
FTDI_I2C_SCL: USB Control FTDI (R35.2 U10.3), Comms LVL Shift and MUX (U13.7)
FTDI_SCLK_SHIFT: USB Control FTDI (R36.2), Comms LVL Shift and MUX (R52.1 U14.3)
FTDI_SDI_SHIFT: USB Control FTDI (U11.19), Comms LVL Shift and MUX (R54.1 U14.6)
FTDI_SDO_SHIFT: USB Control FTDI (U11.18), Comms LVL Shift and MUX (U14.5)
IOVDD_PG: Power LDO (Q3.1 R24.1 U8.4), DUT IO (U20.1)
ISENSE_AVDD: Power LDO (U5.4), Power Sense ADC (U9.9)
ISENSE_IOVDD: Power LDO (U7.4), Power Sense ADC (U9.5)
PDN/SYNC: DUT IO (J12.3), FMC+ Sections F-H, J, K (R142.1)
PG-M2C: FMC+ Sections A-E (R138.1), FMC+ Sections F-H, J, K (J1.F1)
SCL_I2C: Power Sense ADC (U9.14), Comms LVL Shift and MUX (PP6.1 U13.6), FMC+ Sections A-E (U22.6)
SCLK_DUT: Comms LVL Shift and MUX (PP7.1 U15.2), DUT IO (R126.1)
SDA_I2C: Power Sense ADC (U9.13), Comms LVL Shift and MUX (PP5.1 U13.10), FMC+ Sections A-E (U22.5)
SDIO_DUT: Comms LVL Shift and MUX (PP9.1 U15.7), DUT IO (R127.1)
SEN_DUT: Comms LVL Shift and MUX (PP8.1 U15.5), DUT IO (R129.1)
USB_I2C_SDAr: USB Control FTDI (R38.2 R40.2 U11.28), Comms LVL Shift and MUX (U13.9)

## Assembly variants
001 ADC3663: not fitted C63 C71 C84 FID1 FID2 FID3 R10 R15 R23 R60 R63 R65 R66 R83 R91 R95 R101 R103 R109 R110 R112 R150 R180 TP1 TP2; alternate parts U1 -> ADC3663IRSB
002 ADC3664: not fitted C63 C71 C84 FID1 FID2 FID3 R10 R15 R23 R60 R63 R65 R66 R83 R91 R95 R103 R107 R109 R110 R112 R150 R180 TP1 TP2; alternate parts L2 -> indrf00701, L3 -> LQG15HS82NJ02D, L4 -> LQG15HS82NJ02D, L2 -> LQG15HS82NJ02D, L1 -> LQG15HS82NJ02D
003 ADC3683: not fitted C63 C71 C84 FID1 FID2 FID3 R10 R15 R23 R60 R63 R65 R66 R83 R91 R95 R101 R103 R107 R110 R112 R150 R180 TP1 TP2; alternate parts U1 -> ADC3683IRSB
